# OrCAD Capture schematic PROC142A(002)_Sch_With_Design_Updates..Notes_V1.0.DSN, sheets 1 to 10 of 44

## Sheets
1 28. AUTOMATION SIGNALS BUFFER: size C; title: AUTOMATION SIGNALS BUFFER; rev: A1
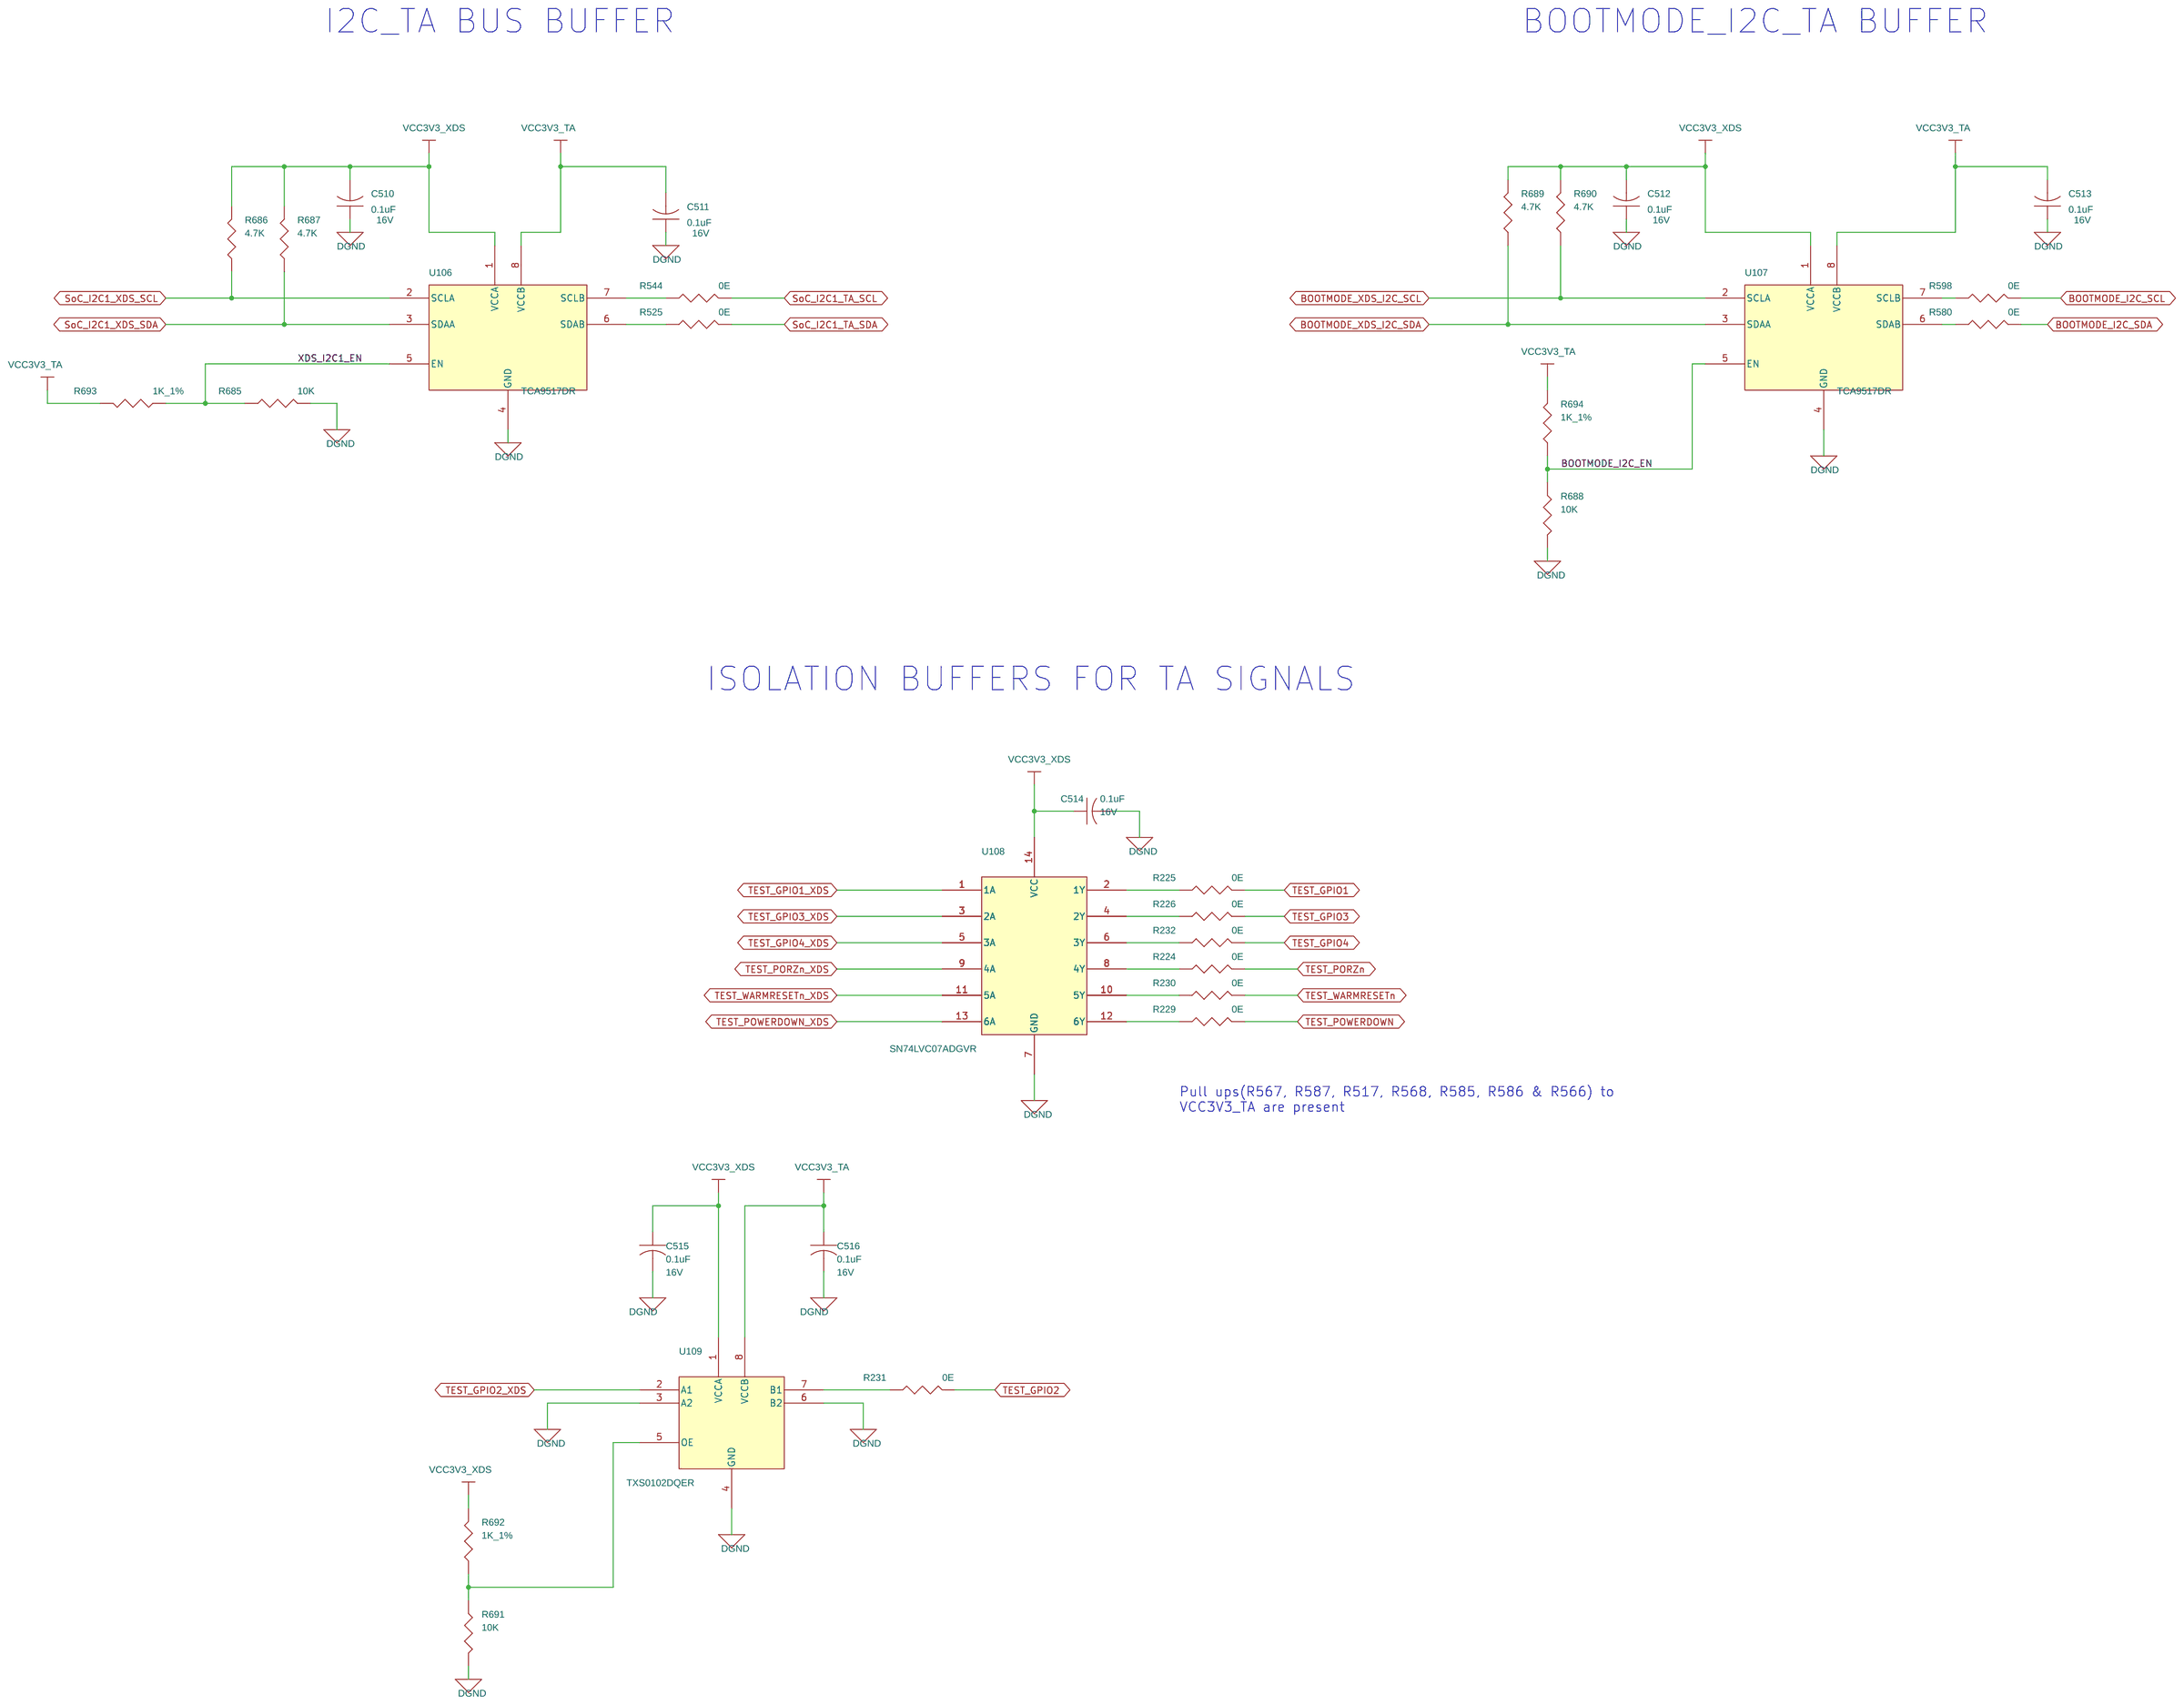
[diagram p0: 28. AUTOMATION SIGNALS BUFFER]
2 01. TABLE OF CONTENTS: title: TABLE OF CONTENTS
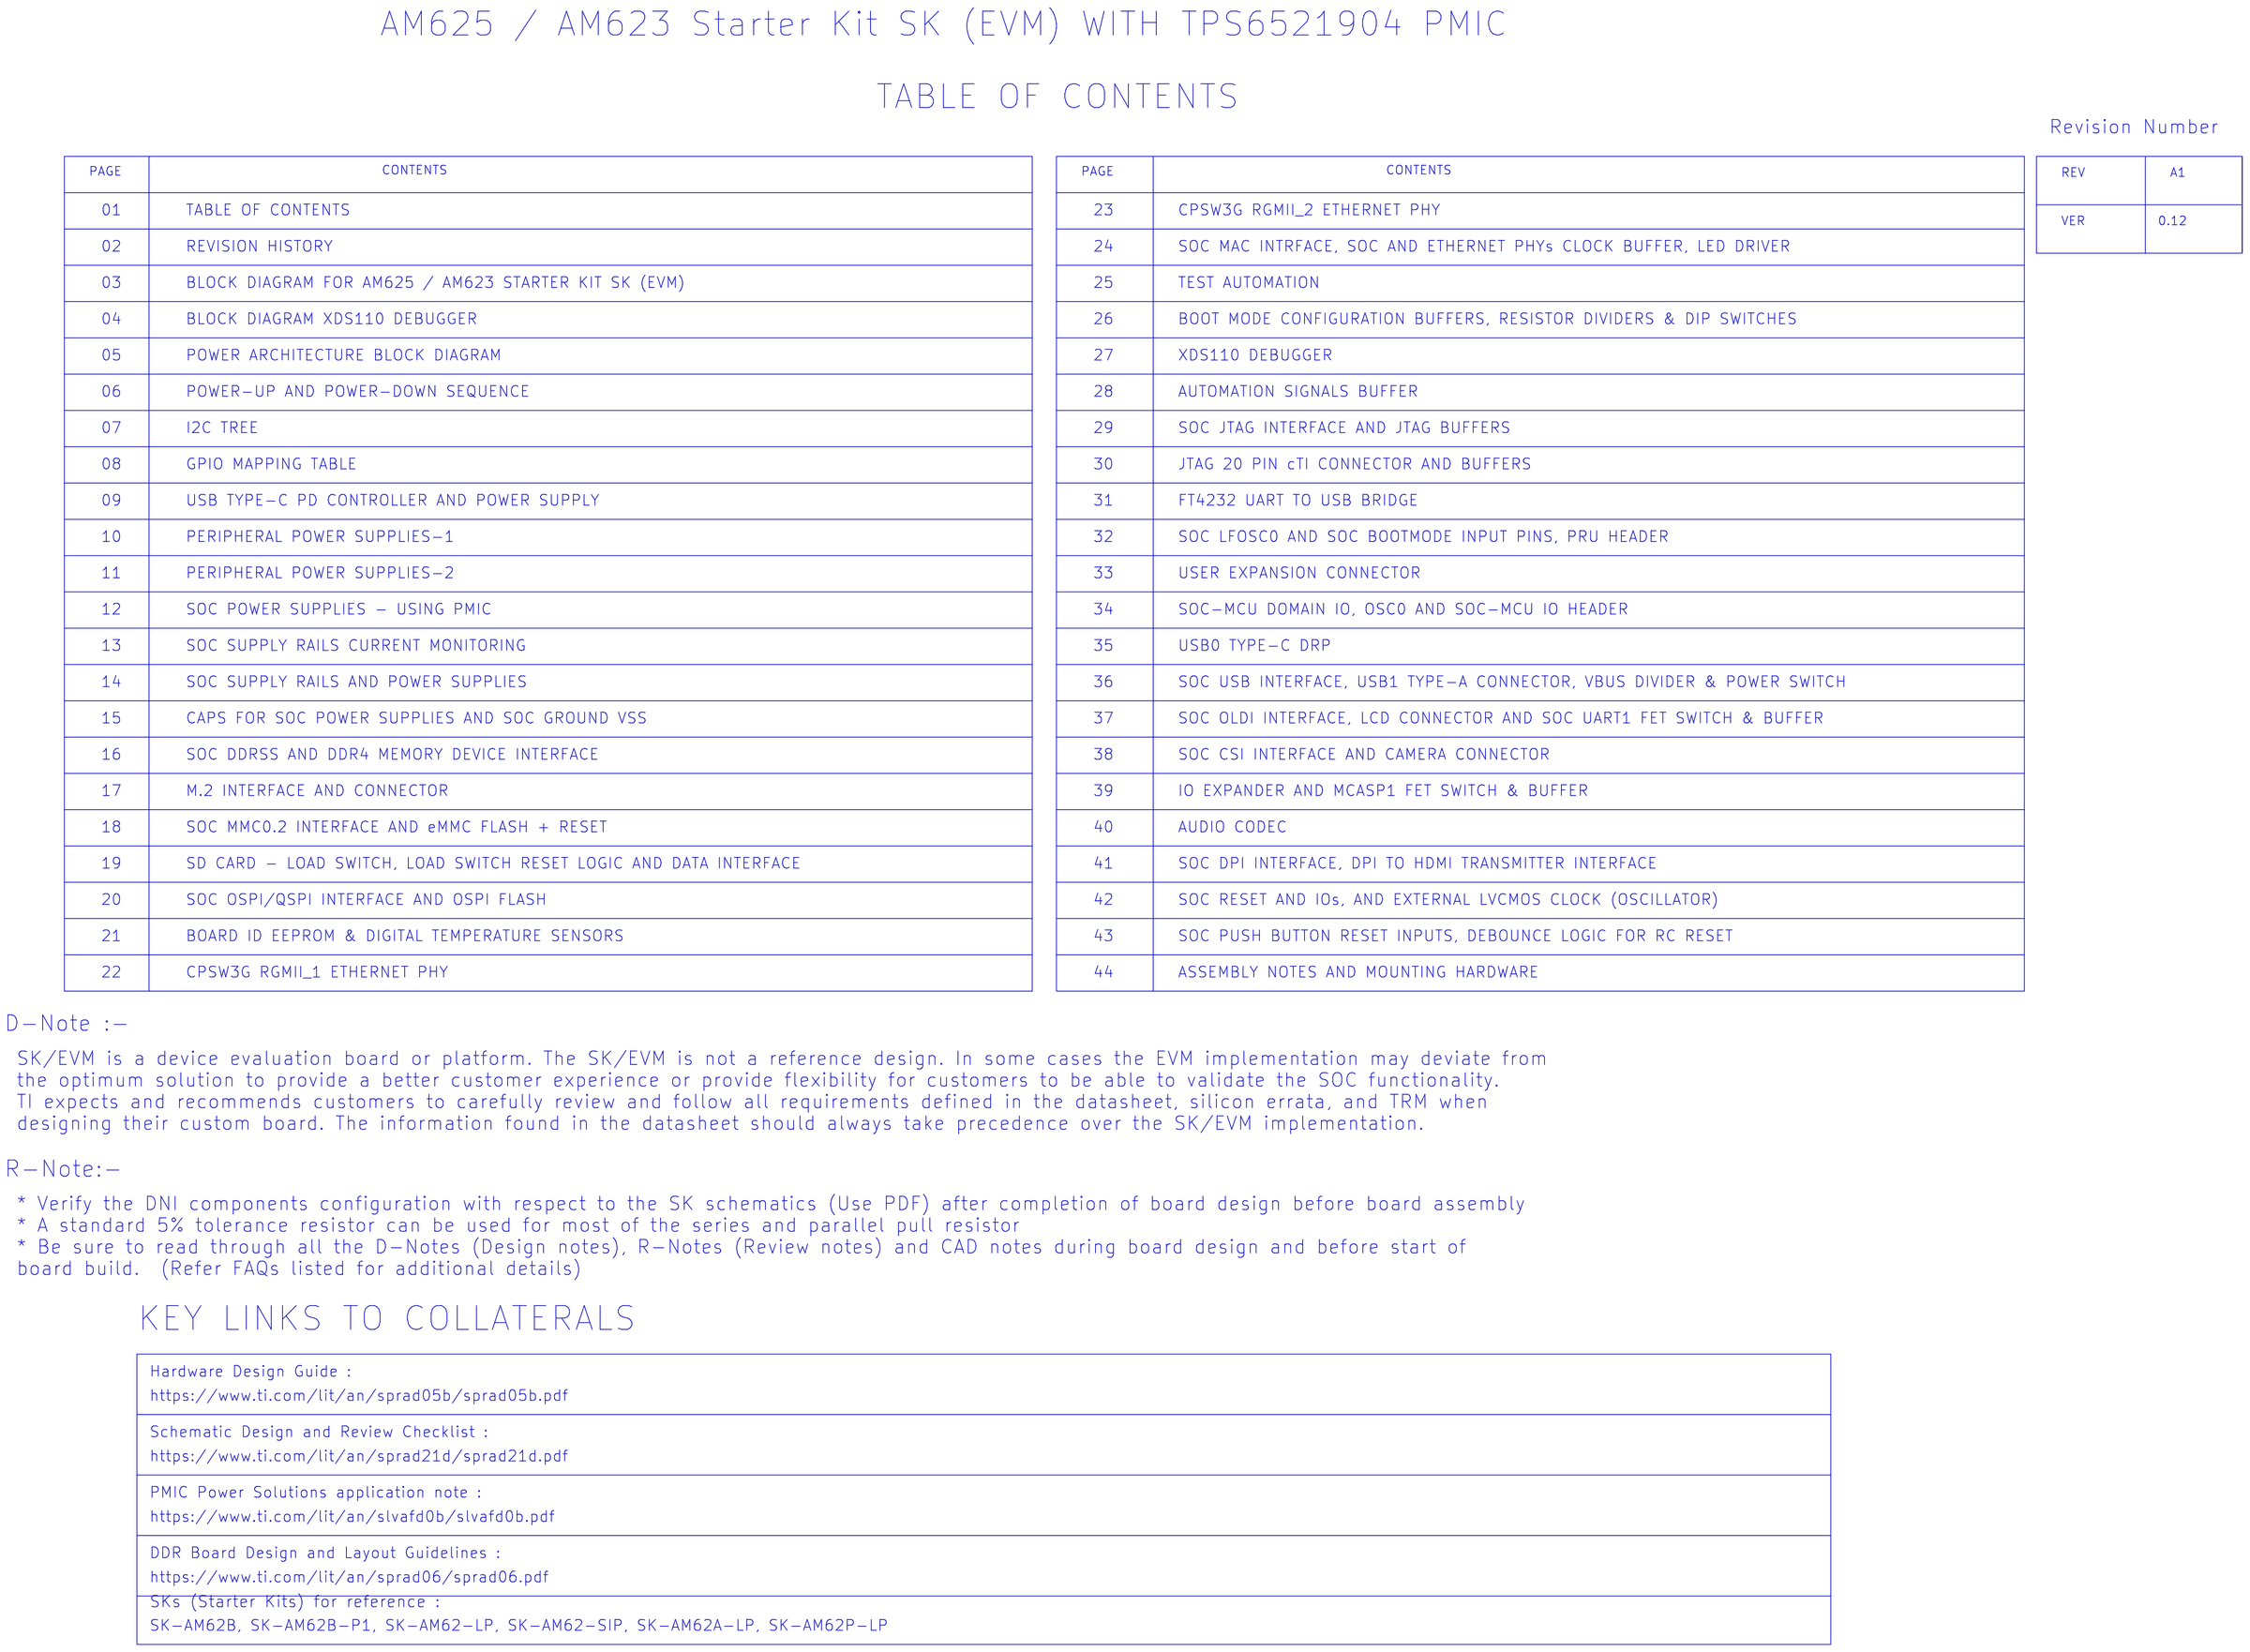
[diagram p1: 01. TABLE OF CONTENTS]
3 02. REVISION HISTORY: title: REVISION HISTORY
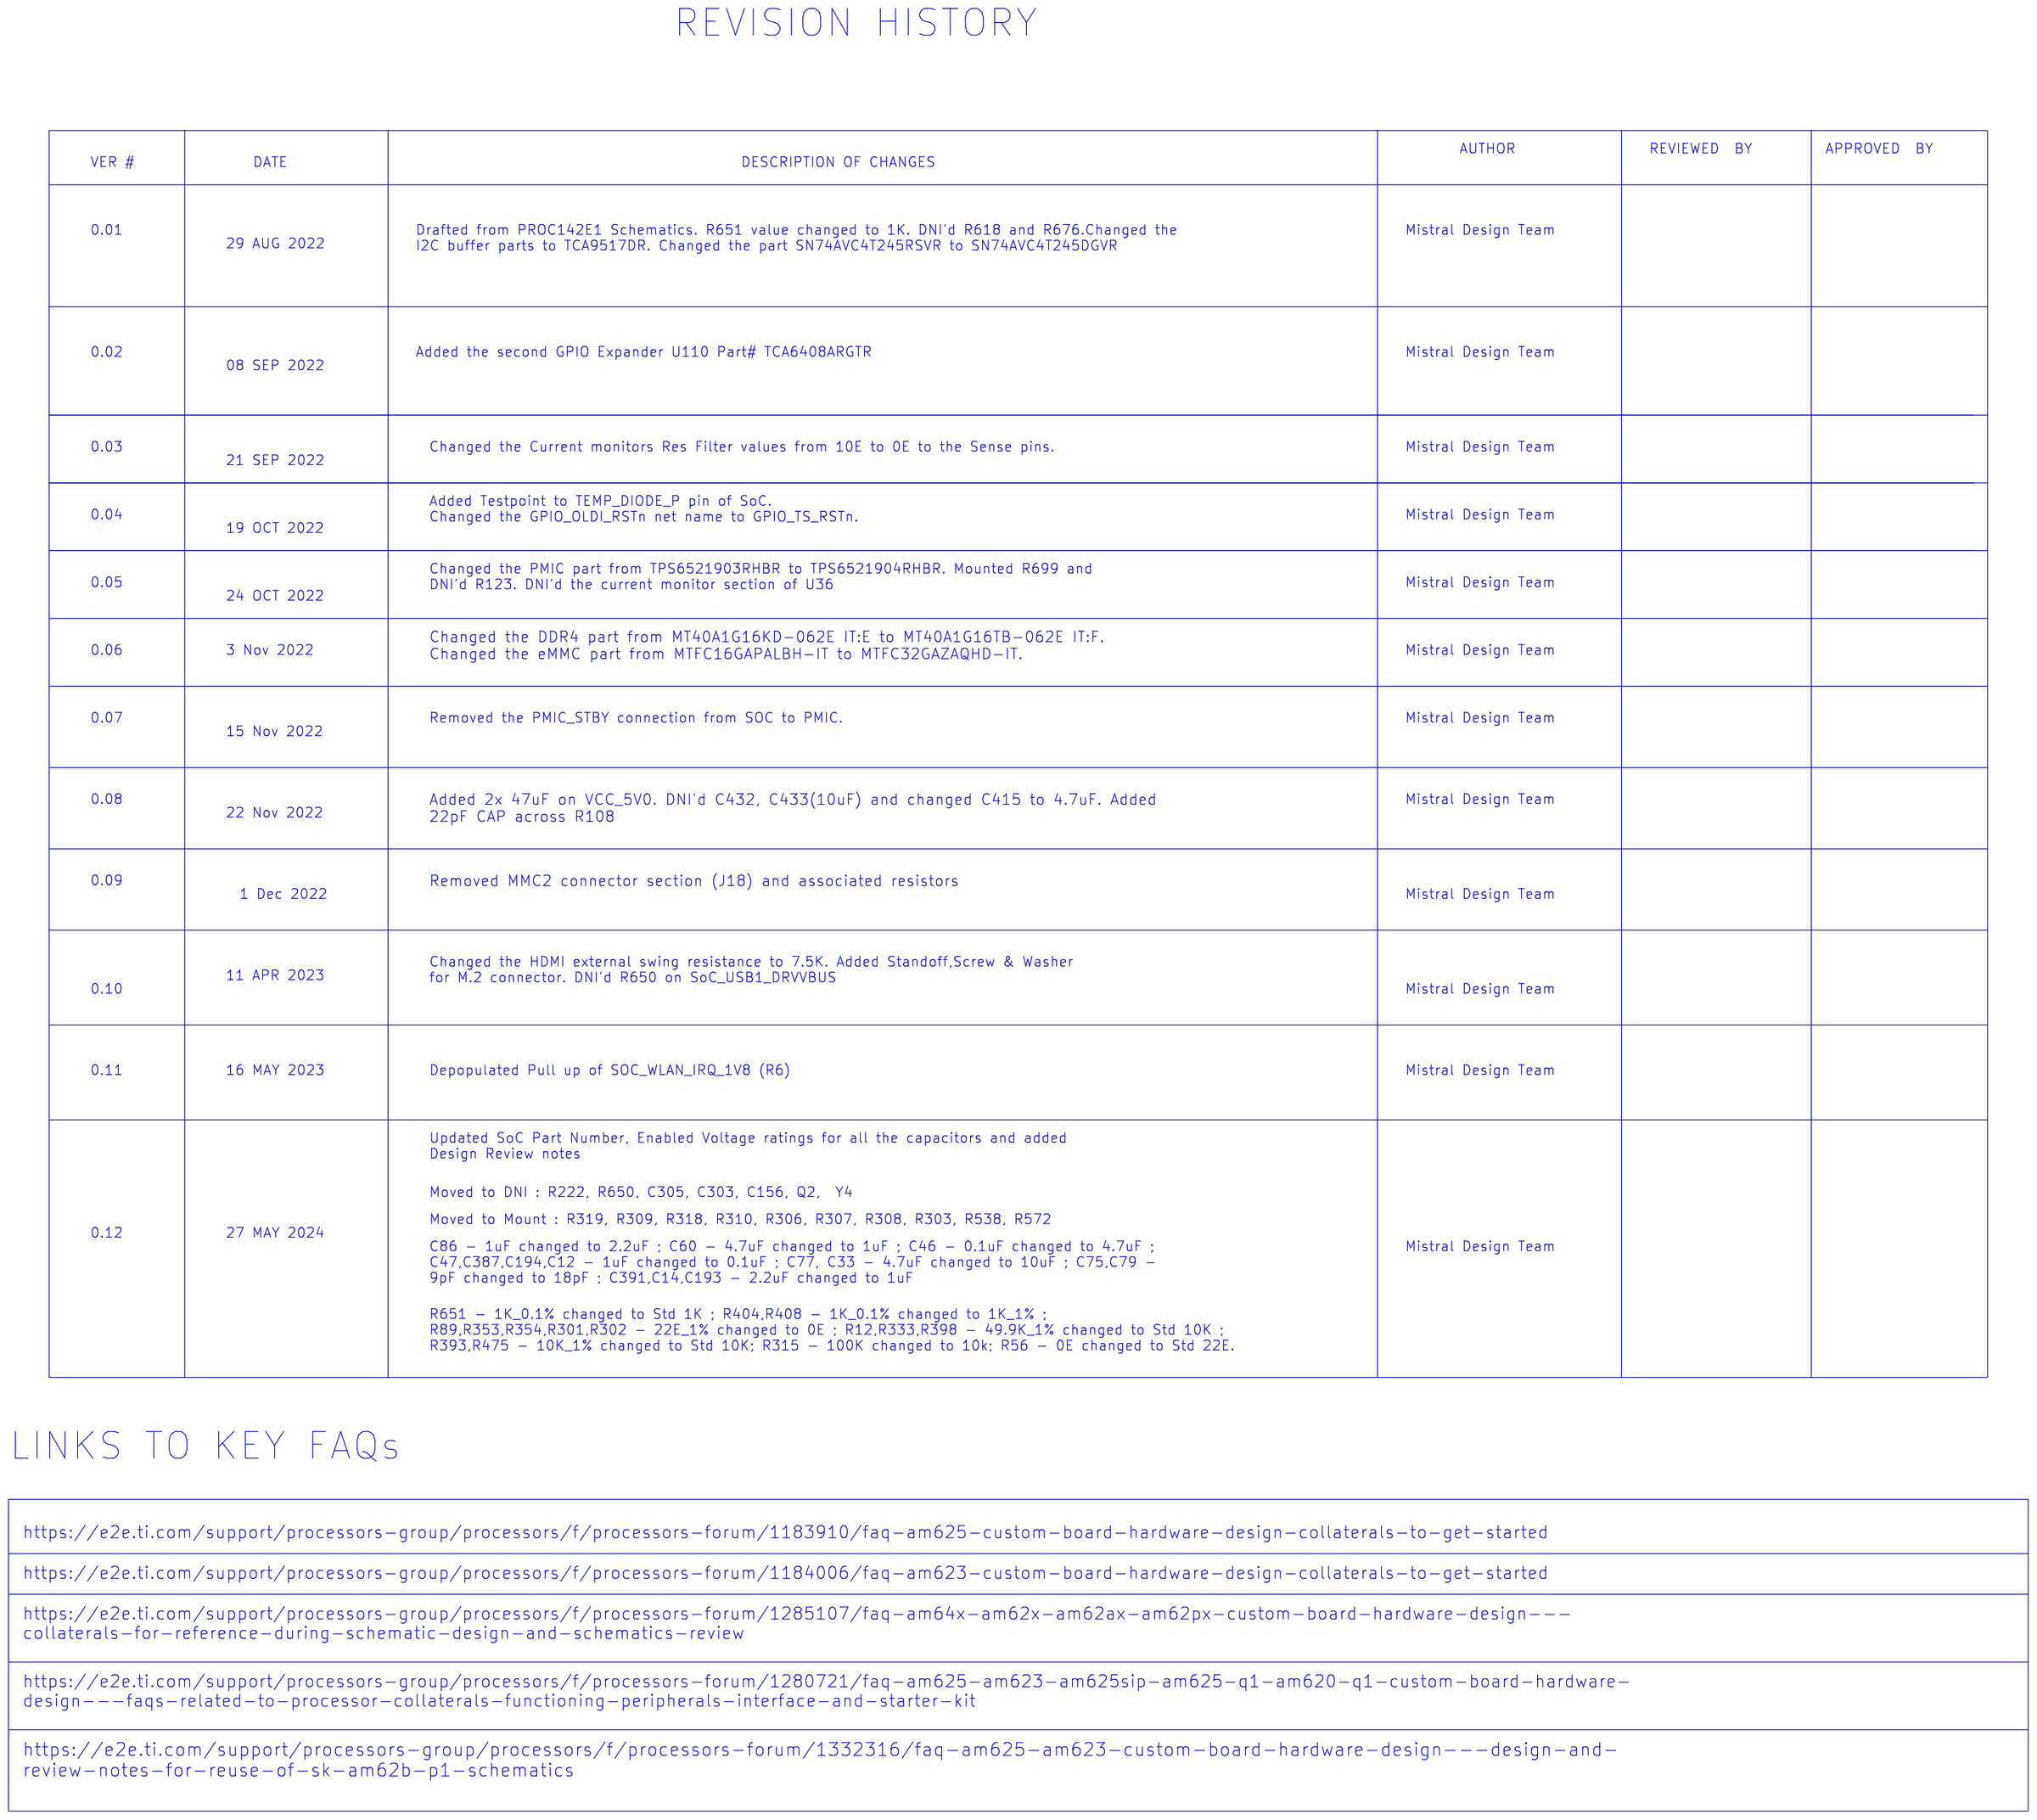
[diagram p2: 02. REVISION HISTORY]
4 03. BLOCK DIAGRAM AM62x_SKEVM: title: BLOCK DIAGRAM AM62x SKEVM
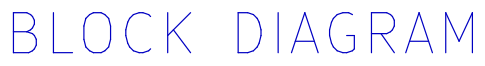
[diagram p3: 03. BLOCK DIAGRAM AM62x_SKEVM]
5 04. BLOCK DIAGRAM_XDS110: title: BLOCK DIAGRAM_XDS110
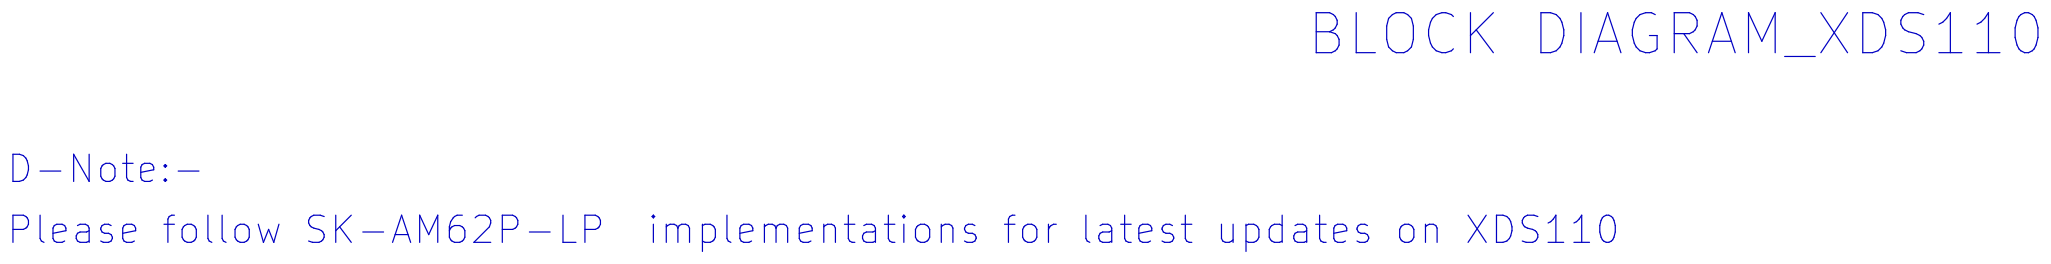
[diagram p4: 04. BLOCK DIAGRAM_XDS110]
6 05. POWER BLOCK DIAGRAM: title: POWER BLOCK DIAGRAM
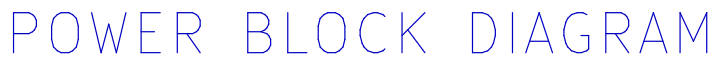
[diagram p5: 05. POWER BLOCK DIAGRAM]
7 06. POWER SEQUENCE: title: POWER SEQUENCE
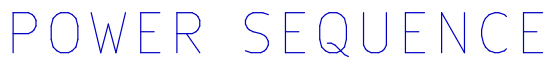
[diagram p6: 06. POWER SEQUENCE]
8 07. I2C TREE: title: I2C TREE
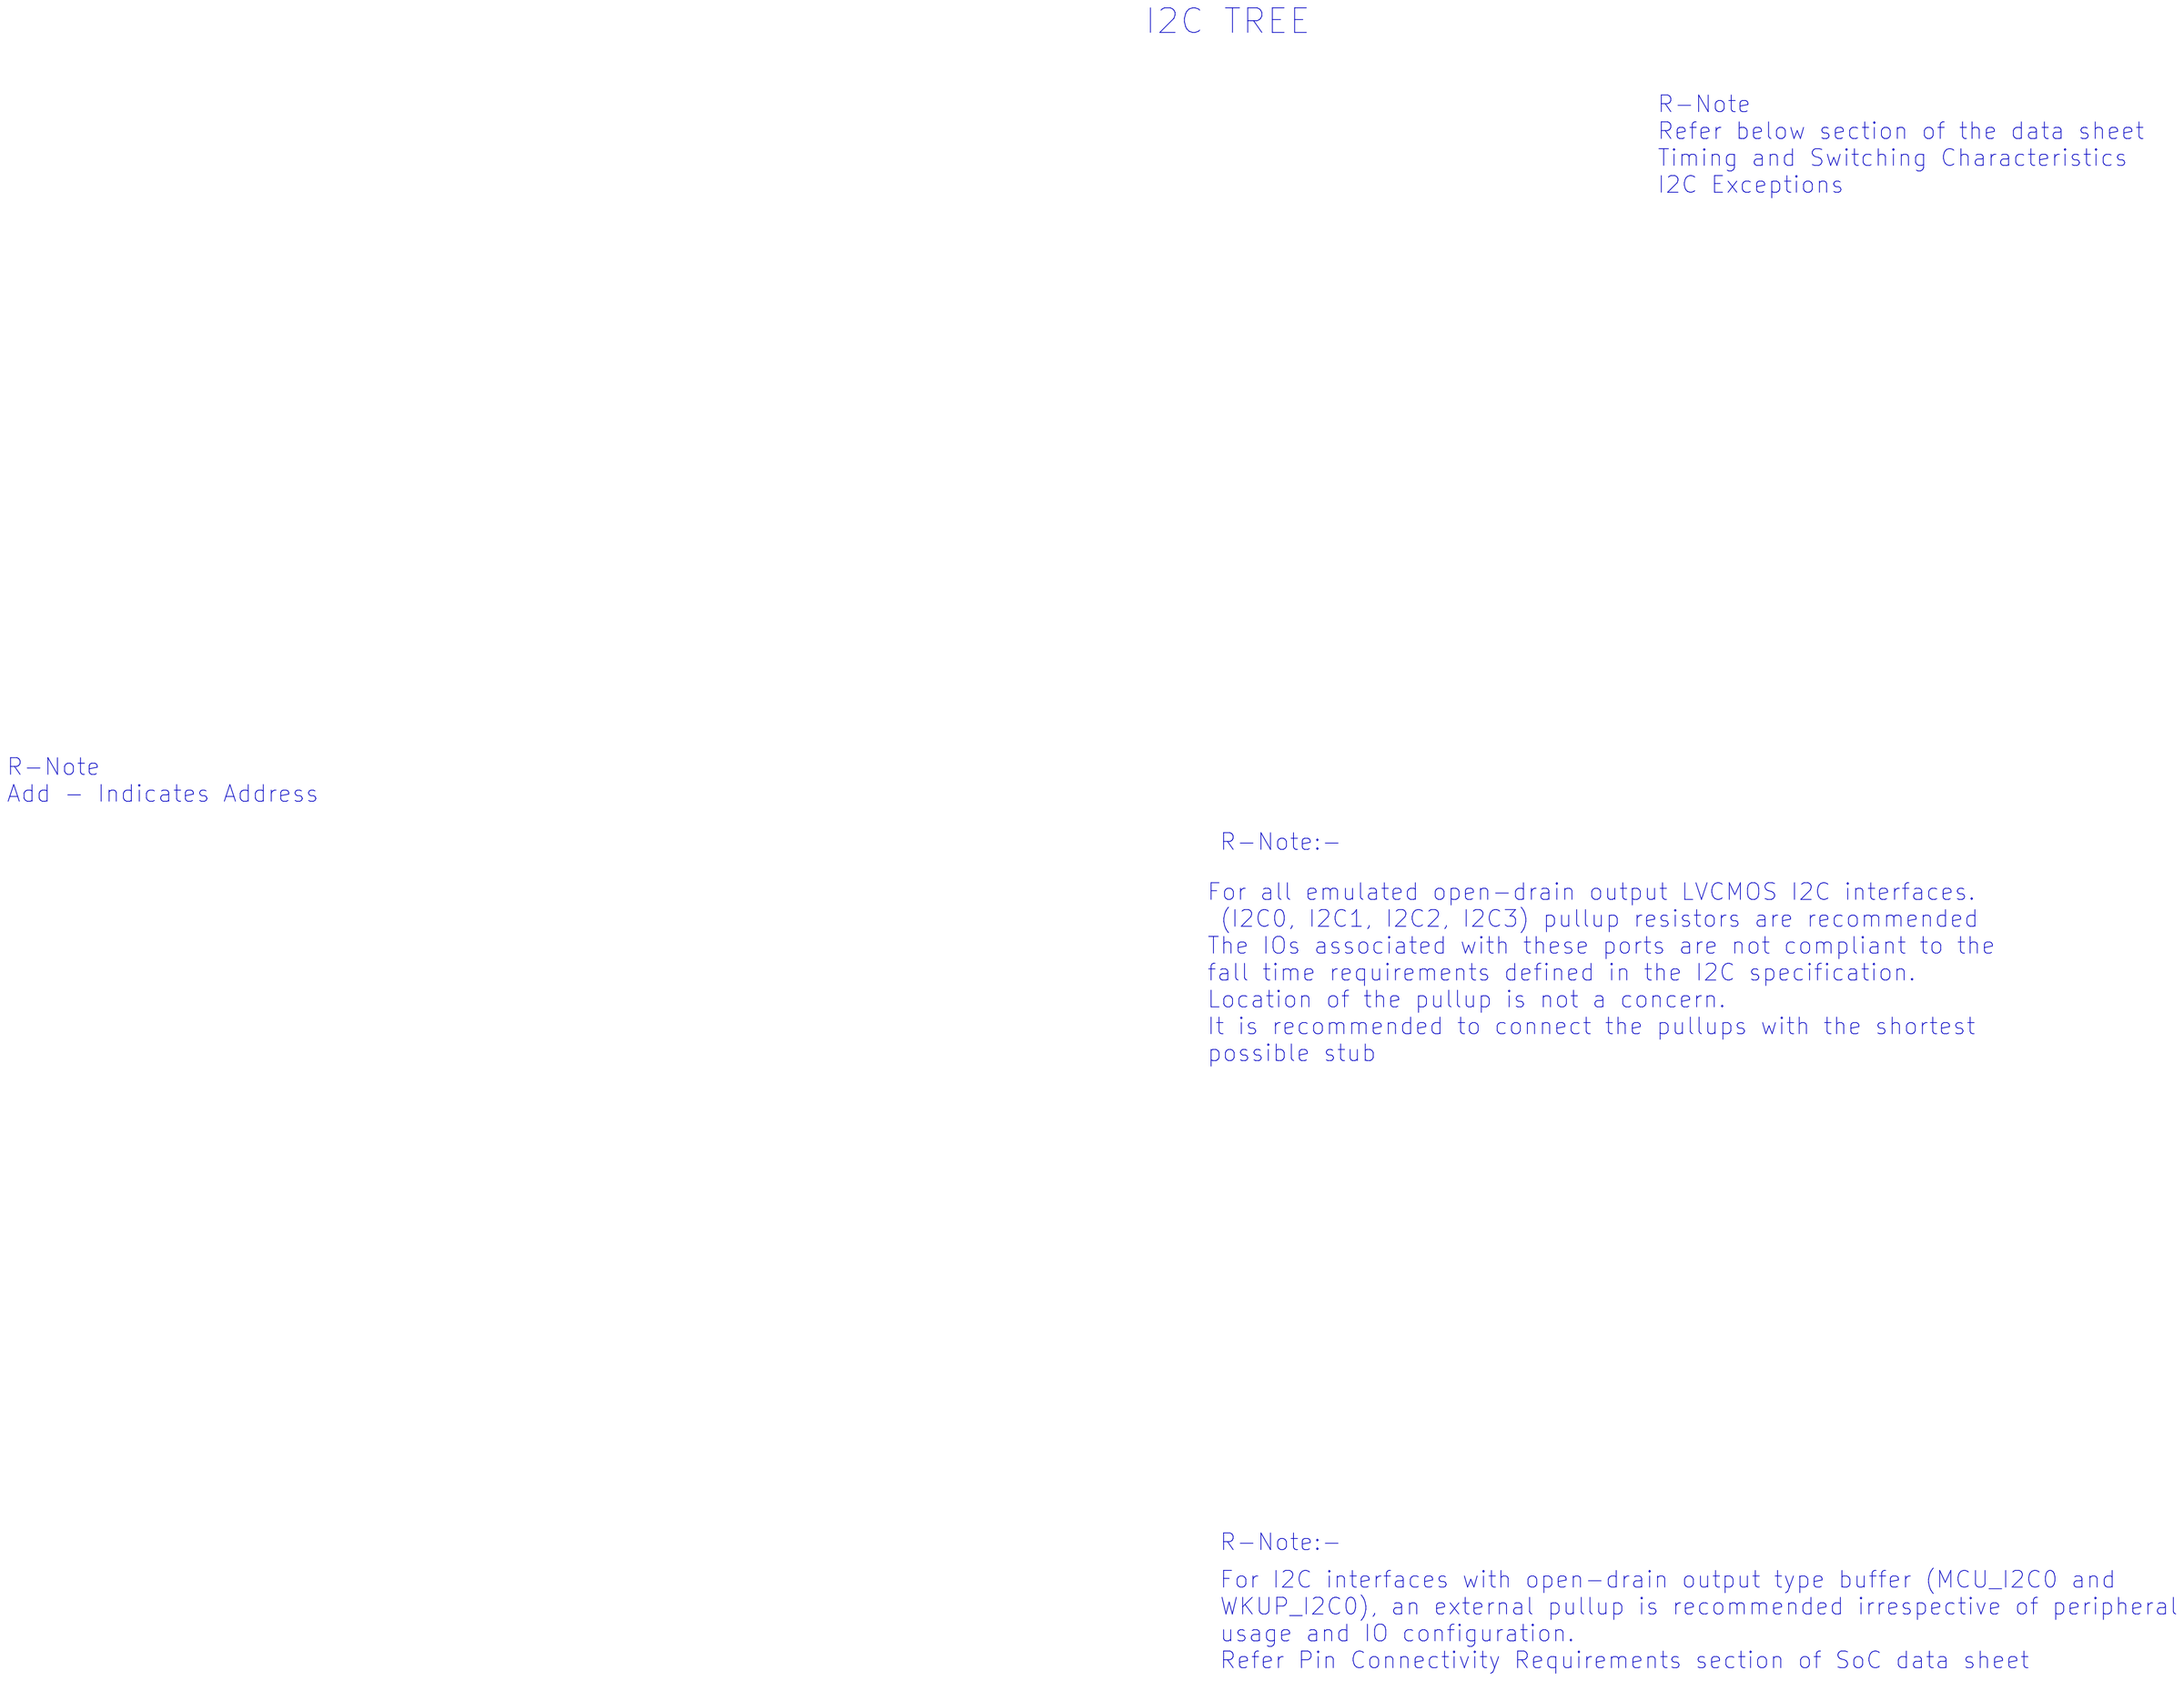
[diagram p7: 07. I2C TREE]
9 08. GPIO MAPPING TABLE: title: GPIO MAPPING TABLE
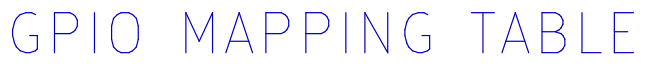
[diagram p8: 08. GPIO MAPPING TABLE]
10 09. USB TYPE-C POWER: size C; title: USB TYPE-C POWER
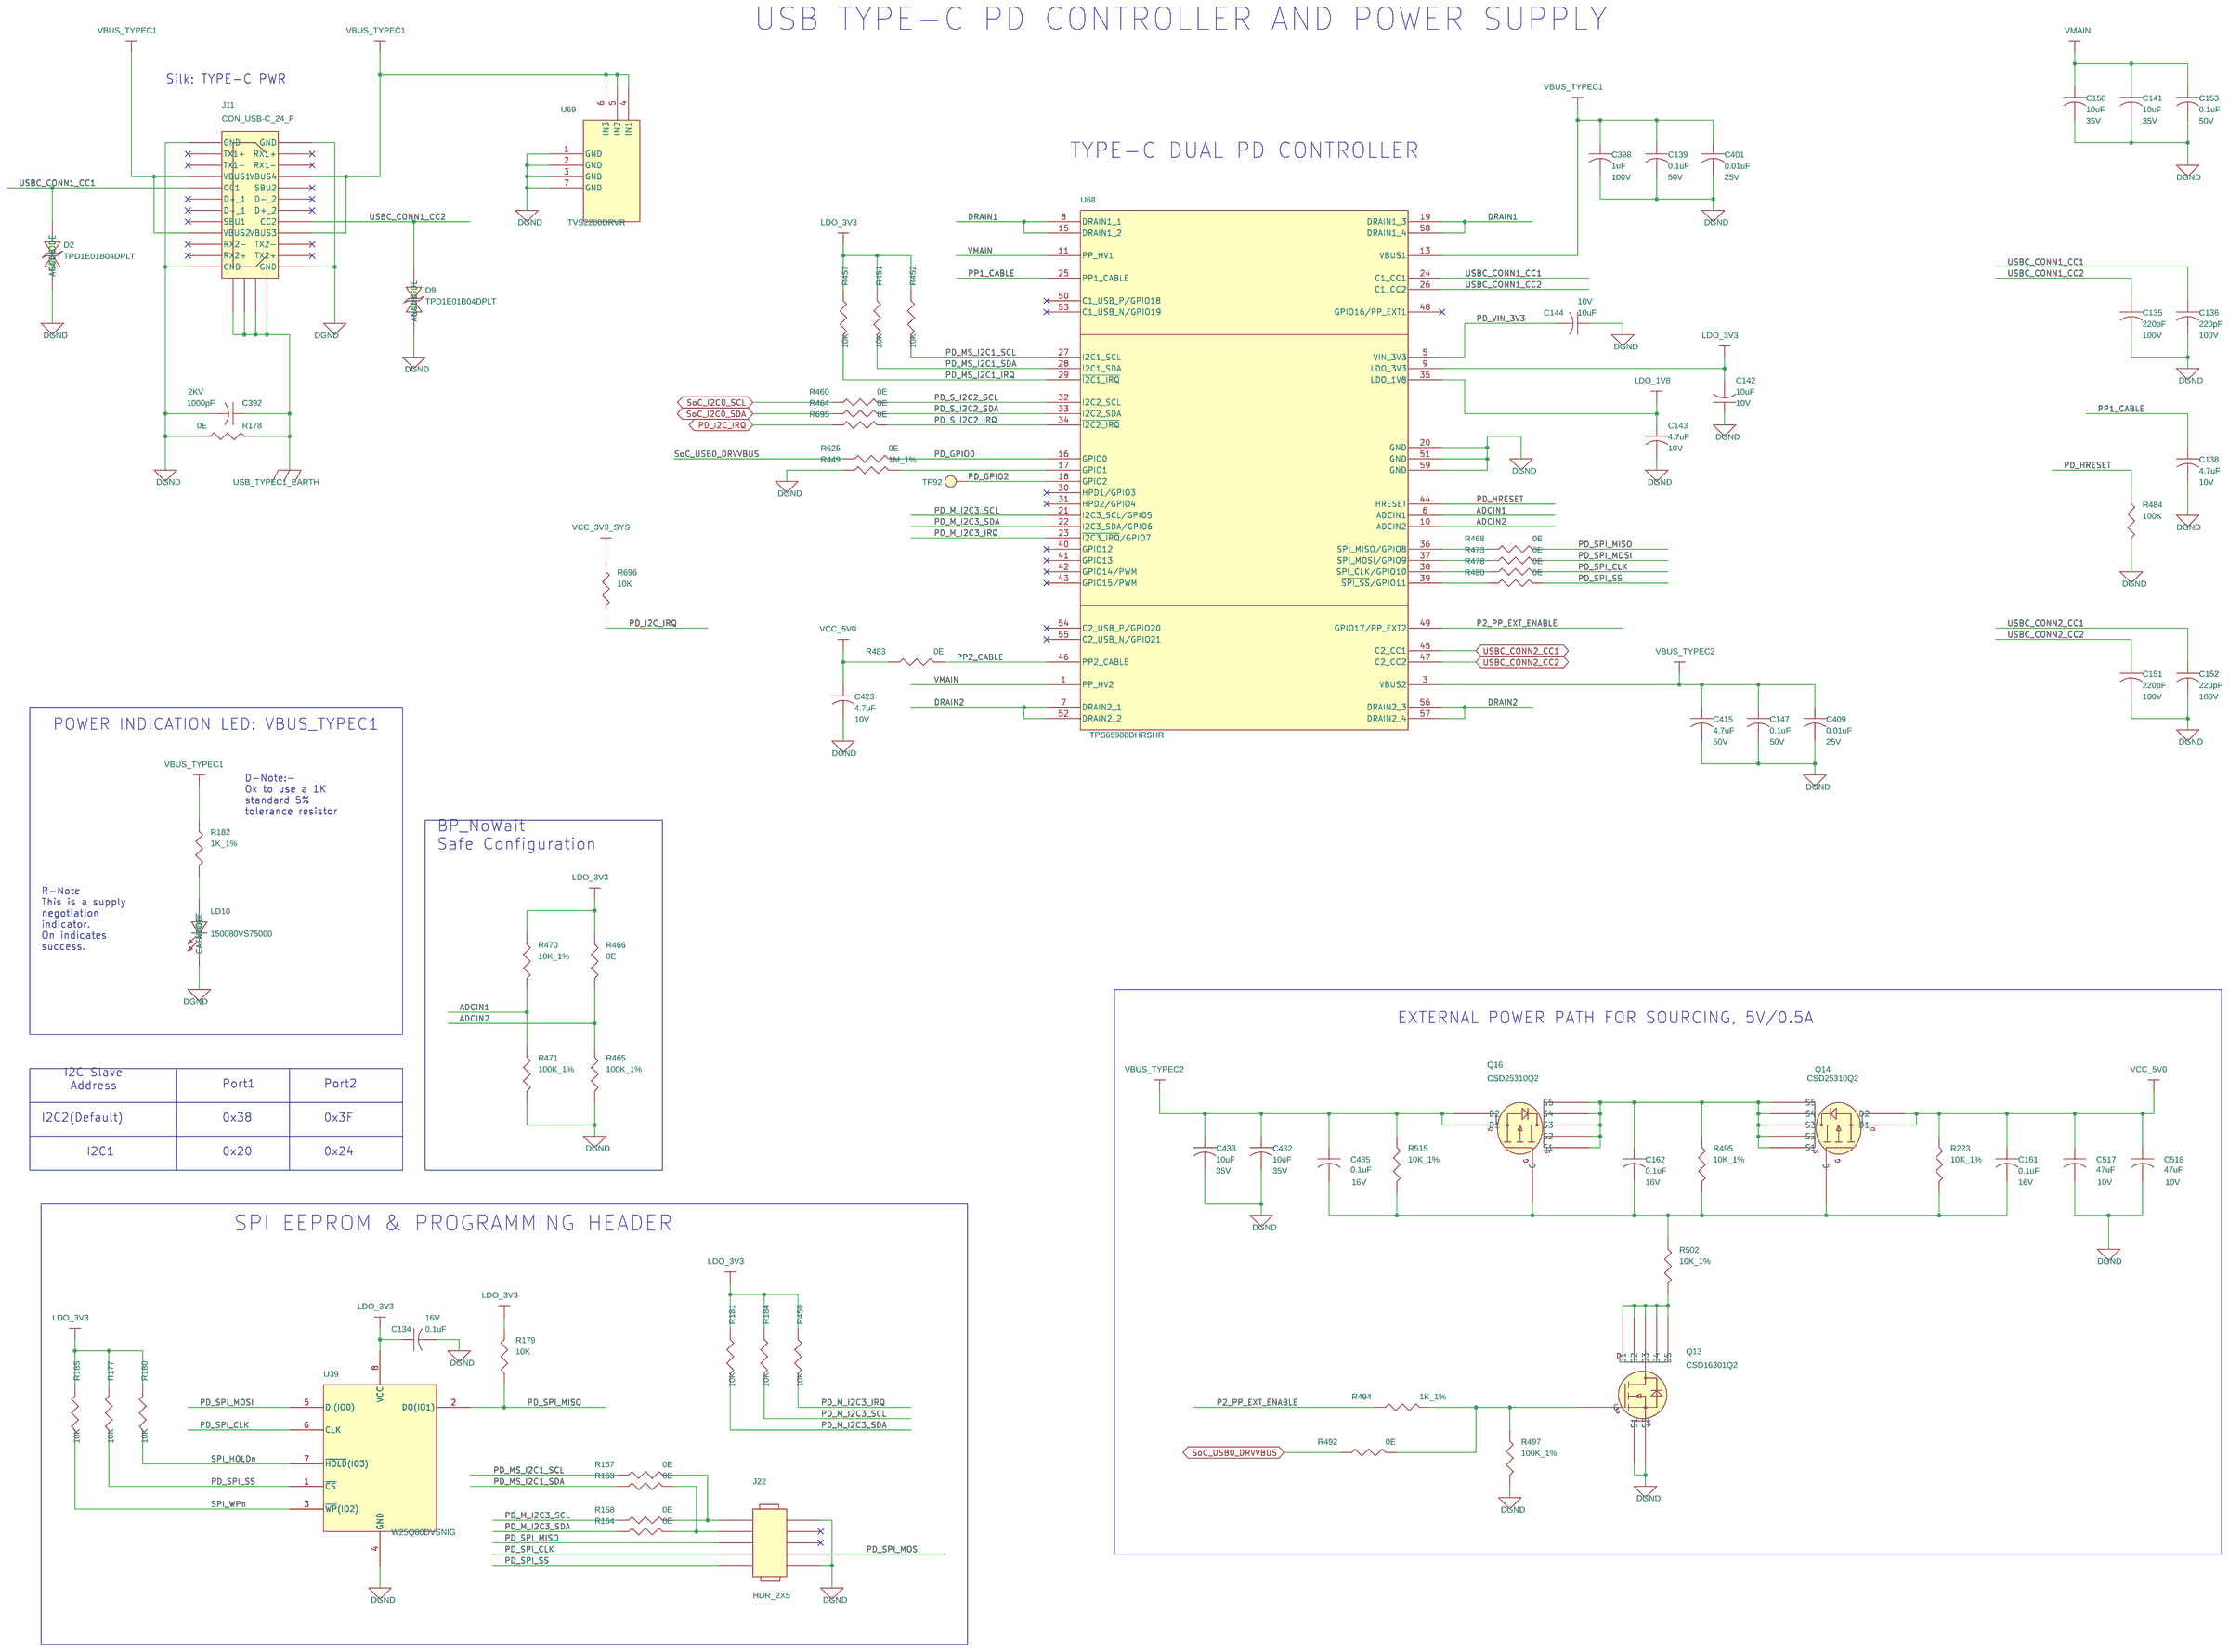
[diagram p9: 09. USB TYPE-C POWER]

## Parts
sheet 09. USB TYPE-C POWER
C134  0.1uF  [CAP0201_0-5]
C135  220pF  [CAP0402_0-75]
C136  220pF  [CAP0402_0-75]
C138  4.7uF  [CAP0402_0-75]
C139  0.1uF  [CAP0402_0-75]
C141  10uF  [CAP0603_1]
C142  10uF  [CAP0402_0-75]
C143  4.7uF  [CAP0402_0-75]
C144  10uF  [CAP0402_0-75]
C147  0.1uF  [CAP0402_0-75]
C150  10uF  [CAP0603_1]
C151  220pF  [CAP0402_0-75]
C152  220pF  [CAP0402_0-75]
C153  0.1uF  [CAP0402_0-75]
C161  0.1uF  [CAP0201_0-5]
C162  0.1uF  [CAP0201_0-5]
C392  1000pF  [CAP1206_1-75]
C398  1uF  [CAP0805_1-5]
C401  0.01uF  [CAP0201_0-5]
C409  0.01uF  [CAP0201_0-5]
C415  4.7uF  [CAP0805_1-5]
C423  4.7uF  [CAP0402_0-75]
C432  10uF  [CAP0603_1]
C433  10uF  [CAP0603_1]
C435  0.1uF  [CAP0201_0-5]
C517  47uF  [CAP1206_2]
C518  47uF  [CAP1206_2]
D2  TPD1E01B04DPLT  [DIO_DFN0201_0-4]
D9  TPD1E01B04DPLT  [DIO_DFN0201_0-4]
J11  CON_USB-C_24_F  [CON_USBC24_2012670_S_R_S_3-9]
J22  HDR_2X5  [HDR_2X5_PEC05DAAN_S_T_8-6]
LD10  150080VS75000  [LED_150080VS75000_80X50_SMD_0-8]
Q13  CSD16301Q2  [WSON6_CSD13202Q2_80X80_0-8]
Q14  CSD25310Q2  [SON6_CSD17313Q2_80X80]
Q16  CSD25310Q2  [SON6_CSD17313Q2_80X80]
R157  0E  [RES0201_0-5]
R158  0E  [RES0201_0-5]
R163  0E  [RES0201_0-5]
R164  0E  [RES0201_0-5]
R177  10K  [RES0201_0-5]
R178  0E  [RES0603_0-75]
R179  10K  [RES0201_0-5]
R180  10K  [RES0201_0-5]
R181  10K  [RES0201_0-5]
R182  1K_1%  [RES0402_0-5]
R184  10K  [RES0201_0-5]
R185  10K  [RES0201_0-5]
R223  10K_1%  [RES0201_0-5]
R449  1M_1%  [RES0402_0-5]
R450  10K  [RES0201_0-5]
R451  10K  [RES0201_0-5]
R452  10K  [RES0201_0-5]
R457  10K  [RES0201_0-5]
R460  0E  [RES0201_0-5]
R464  0E  [RES0201_0-5]
R465  100K_1%  [RES0402_0-5]
R466  0E  [RES0201_0-5]
R468  0E  [RES0201_0-5]
R470  10K_1%  [RES0201_0-5]
R471  100K_1%  [RES0402_0-5]
R473  0E  [RES0201_0-5]
R478  0E  [RES0201_0-5]
R480  0E  [RES0201_0-5]
R483  0E  [RES0402_0-5]
R484  100K  [RES0201_0-5]
R492  0E  [RES0201_0-5]
R494  1K_1%  [RES0402_0-5]
R495  10K_1%  [RES0201_0-5]
R497  100K_1%  [RES0402_0-5]
R502  10K_1%  [RES0201_0-5]
R515  10K_1%  [RES0201_0-5]
R625  0E  [RES0201_0-5]
R695  0E  [RES0201_0-5]
R696  10K  [RES0201_0-5]
TP92  TP20_SMD  [TP20_SMD]
U39  W25Q80DVSNIG  [SOIC8_1-8]
U68  TPS65988DHRSHR  [VQFN56_TPS65987D_280X280_1]
U69  TVS2200DRVR  [SON6_25-59_85X85_0-8]
sheet 28. AUTOMATION SIGNALS BUFFER
C510  0.1uF  [CAP0201_0-5]
C511  0.1uF  [CAP0201_0-5]
C512  0.1uF  [CAP0201_0-5]
C513  0.1uF  [CAP0201_0-5]
C514  0.1uF  [CAP0201_0-5]
C515  0.1uF  [CAP0201_0-5]
C516  0.1uF  [CAP0201_0-5]
R224  0E  [RES0201_0-5]
R225  0E  [RES0201_0-5]
R226  0E  [RES0201_0-5]
R229  0E  [RES0201_0-5]
R230  0E  [RES0201_0-5]
R231  0E  [RES0201_0-5]
R232  0E  [RES0201_0-5]
R525  0E  [RES0201_0-5]
R544  0E  [RES0201_0-5]
R580  0E  [RES0201_0-5]
R598  0E  [RES0201_0-5]
R685  10K  [RES0201_0-5]
R686  4.7K  [RES0201_0-5]
R687  4.7K  [RES0201_0-5]
R688  10K  [RES0201_0-5]
R689  4.7K  [RES0201_0-5]
R690  4.7K  [RES0201_0-5]
R691  10K  [RES0201_0-5]
R692  1K_1%  [RES0402_0-5]
R693  1K_1%  [RES0402_0-5]
R694  1K_1%  [RES0402_0-5]
U106  TCA9517DR  [SOIC8_1-8]
U107  TCA9517DR  [SOIC8_1-8]
U108  SN74LVC07ADGVR  [TVSOP14_15-74_180X150_1-2]
U109  TXS0102DQER  [X2SON8_TXS0102_40X60_0-4]

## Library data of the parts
C134 C161 C162 C435 = CAP: CAP CERAMIC 0.1uF 16V 10% X5R 0201; Chkd/date: MANIRAJA/230118; Crtd /date: MANIRAJA/230118; Custom_Duty: 15%; Customs_HS_Code: 85322990; Distributor_name: DIGIKEY; Distributor_part_number: 490-14305-1-ND; Footprint Path: Y:\MIS_DATABASE\Library\ALTIUM_TOOL\PCB_FOOTPRINTS\Altium_Footprint_Lib.PcbLib; Height: 0.33MM; Library Path: Y:\MIS_DATABASE\Library\ALTIUM_TOOL\SCHEMATICS_PARTS\MS_DISCRETE_Library.schlib; Mfr_name: MURATA; Mfr_part_number: GRM033R61C104KE14D; Mistral Part No: 120009030072-R; Package: 0201; Part_type: CAPACITORS\CERAMIC; Project: TI_MAXIE_CPB; RoHS: RoHS; Temperature: -55°C+85°C; Tolerance: 10%; Voltage: 16V; Wattage: NA; Weight: 0.33mg; Datasheet: Y:\MIS_DATABASE\DATASHEETS\CAPACITORS\GRM033R61C104KE14.PDF
C135 C136 C151 C152 = CAP: CAP CERAMIC 220pF 100V 5% C0G(NP0) 0402; Chkd/date: MANIRAJA/061021; Crtd /date: ALVY/051021; Custom_Duty: 15%; Customs_HS_Code: 85322990; Distributor_name: DIGIKEY; Distributor_part_number: 490-GRM1555C2A221JE01DTR-ND; Footprint Path: Y:\MIS_DATABASE\Library\ALTIUM_TOOL\PCB_FOOTPRINTS\Altium_Footprint_Lib.PcbLib; Height: 0.55MM; Library Path: Y:\MIS_DATABASE\Library\ALTIUM_TOOL\SCHEMATICS_PARTS\MS_DISCRETE_Library.schlib; Mfr_name: MURATA; Mfr_part_number: GRM1555C2A221JE01D; Mistral Part No: 120021100001-R; Package: 0402; Part_type: CAPACITORS\CERAMIC; Project: TI_AM62x SKEVM_BRD; RoHS: RoHS; Temperature: -55°C+125°C; Tolerance: 5%; Voltage: 100V; Wattage: NA; Weight: 1.6mg; Datasheet: Y:\MIS_DATABASE\DATASHEETS\CAPACITORS\GRM1555C2A221JE01.PDF
C138 C143 C423 = CAP: CAP CERAMIC 4.7uF 10V 20% X5R 0402; Chkd/date: MANIRAJA/110718; Crtd /date: ALVY/110718; Custom_Duty: 15%; Customs_HS_Code: 85322990; Distributor_name: DIGIKEY; Distributor_part_number: 490-14306-1-ND; Footprint Path: Y:\MIS_DATABASE\Library\ALTIUM_TOOL\PCB_FOOTPRINTS\Altium_Footprint_Lib.PcbLib; Height: 0.65MM; Library Path: Y:\MIS_DATABASE\Library\ALTIUM_TOOL\SCHEMATICS_PARTS\MS_DISCRETE_Library.schlib; Mfr_name: MURATA; Mfr_part_number: GRM155R61A475MEAAD; Mistral Part No: 120012060002-R; Package: 0402; Part_type: CAPACITORS\CERAMIC; Project: TI_J7SVB_PCIE_ADD-ON-CARD; RoHS: RoHS; Temperature: -55°C+85°C; Tolerance: 20%; Voltage: 10V; Wattage: NA; Weight: 14mg; Datasheet: Y:\MIS_DATABASE\DATASHEETS\CAPACITORS\GRM155R61A475MEAAD.PDF
C139 C147 C153 = CAP: CAP CERAMIC 0.1uF 50V 10% X7R 0402; Chkd/date: MANIRAJA/261020; Crtd /date: ALVY/211020; Custom_Duty: 15%; Customs_HS_Code: 85322990; Distributor_name: DIGIKEY; Distributor_part_number: 490-10700-1-ND; Footprint Path: Y:\MIS_DATABASE\Library\ALTIUM_TOOL\PCB_FOOTPRINTS\Altium_Footprint_Lib.PcbLib; Height: 0.55MM; Library Path: Y:\MIS_DATABASE\Library\ALTIUM_TOOL\SCHEMATICS_PARTS\MS_DISCRETE_Library.schlib; Mfr_name: MURATA; Mfr_part_number: GRM155R71H104KE14D; Mistral Part No: 120011100014-R; Package: 0402; Part_type: CAPACITORS\CERAMIC; Project: J7_CP; RoHS: RoHS; Temperature: -55°C+125°C; Tolerance: 10%; Voltage: 50V; Wattage: NA; Weight: 3.1mg; Datasheet: Y:\MIS_DATABASE\DATASHEETS\CAPACITORS\GRM155R71H104KE14.PDF
C141 C150 C432 C433 = CAP: CAP CERAMIC 10uF 35V 20% X5R 0603; Chkd/date: MANIRAJA/170519; Crtd /date: ALVY/160519; Custom_Duty: 15%; Customs_HS_Code: 85322990; Distributor_name: DIGIKEY; Distributor_part_number: 490-13248-1-ND; Footprint Path: Y:\MIS_DATABASE\Library\ALTIUM_TOOL\PCB_FOOTPRINTS\Altium_Footprint_Lib.PcbLib; Height: 1.00MM; Library Path: Y:\MIS_DATABASE\Library\ALTIUM_TOOL\SCHEMATICS_PARTS\MS_DISCRETE_Library.schlib; Mfr_name: MURATA; Mfr_part_number: GRM188R6YA106MA73D; Mistral Part No: 120019050016-R; Package: 0603; Part_type: CAPACITORS\CERAMIC; Project: BRUKER_SD820_COMMONDO; RoHS: RoHS; Temperature: -55°C+85°C; Tolerance: 20%; Voltage: 35V; Wattage: NA; Weight: 9mg; Datasheet: Y:\MIS_DATABASE\DATASHEETS\CAPACITORS\GRM188R6YA106MA73.PDF
C142 C144 = CAP: CAP CERAMIC 10uF 10V 20% X5R 0402; Chkd/date: MANIRAJA/300520; Crtd /date: ALVY/260520; Custom_Duty: 15%; Customs_HS_Code: 85322990; Distributor_name: DIGIKEY; Distributor_part_number: 490-GRM155R61A106ME11DTR-ND; Footprint Path: Y:\MIS_DATABASE\Library\ALTIUM_TOOL\PCB_FOOTPRINTS\Altium_Footprint_Lib.PcbLib; Height: 0.55MM; Library Path: Y:\MIS_DATABASE\Library\ALTIUM_TOOL\SCHEMATICS_PARTS\MS_DISCRETE_Library.schlib; Mfr_name: MURATA; Mfr_part_number: GRM155R61A106ME11D; Mistral Part No: 120013110019-R; Package: 0402; Part_type: CAPACITORS\CERAMIC; Project: QCS610_NANOSOM; RoHS: RoHS; Temperature: -55°C+85°C; Tolerance: 20%; Voltage: 10V; Wattage: NA; Weight: 3.1mg; Datasheet: Y:\MIS_DATABASE\DATASHEETS\CAPACITORS\MURATA-GXX-SER_NOV17.PDF
C392 = CAP: CAP CERAMIC 1000pF 2KV 10% X7R 1206; Chkd/date: SHREESHAIL/291106; Crtd /date: MAZHAR/281106; Custom_Duty: 15%; Customs_HS_Code: 85322990; Distributor_name: DIGIKEY; Distributor_part_number: 478-2956-1-ND; Footprint Path: Y:\MIS_DATABASE\Library\ALTIUM_TOOL\PCB_FOOTPRINTS\Altium_Footprint_Lib.PcbLib; Height: 1.52MM; Library Path: Y:\MIS_DATABASE\Library\ALTIUM_TOOL\SCHEMATICS_PARTS\MS_DISCRETE_Library.schlib; Mfr_name: AVX CORPORATION; Mfr_part_number: 1206GC102KAT1A; Mistral Part No: 120015080006-R; Package: 1206; Part_type: CAPACITORS\CERAMIC; Project: ADR1B; RoHS: RoHS; Temperature: -55°C+125°C; Tolerance: 10%; Voltage: 2KV; Wattage: NA; Weight: 16.2mg; Datasheet: Y:\MIS_DATABASE\DATASHEETS\CAPACITORS\AVX_HV-MLC.PDF
C398 = CAP: CAP CERAMIC 1uF 100V 10% X7S 0805; Chkd/date: MANIRAJA/160921; Crtd /date: ALVY/150921; Custom_Duty: 15%; Customs_HS_Code: 85322990; Distributor_name: DIGIKEY; Distributor_part_number: 490-14464-1-ND; Footprint Path: Y:\MIS_DATABASE\Library\ALTIUM_TOOL\PCB_FOOTPRINTS\Altium_Footprint_Lib.PcbLib; Height: 1.45MM; Library Path: Y:\MIS_DATABASE\Library\ALTIUM_TOOL\SCHEMATICS_PARTS\MS_DISCRETE_Library.schlib; Mfr_name: MURATA; Mfr_part_number: GRM21BC72A105KE01L; Mistral Part No: 120013030002-R; Package: 0805; Part_type: CAPACITORS\CERAMIC; Project: TI_AM62x SKEVM_BRD; RoHS: RoHS; Temperature: -55°C+125°C; Tolerance: 10%; Voltage: 100V; Wattage: NA; Weight: 6.4mg; Datasheet: Y:\MIS_DATABASE\DATASHEETS\CAPACITORS\GRM21BC72A105KE01.PDF
C401 C409 = CAP: CAP CERAMIC 0.01uF 25V 10% X5R 0201; Chkd/date: MANIRAJA/230118; Crtd /date: MANIRAJA/230118; Custom_Duty: 15%; Customs_HS_Code: 85322990; Distributor_name: DIGIKEY; Distributor_part_number: GRM033R61E103KA12J-ND; Footprint Path: Y:\MIS_DATABASE\Library\ALTIUM_TOOL\PCB_FOOTPRINTS\Altium_Footprint_Lib.PcbLib; Height: 0.33MM; Library Path: Y:\MIS_DATABASE\Library\ALTIUM_TOOL\SCHEMATICS_PARTS\MS_DISCRETE_Library.schlib; Mfr_name: MURATA; Mfr_part_number: GRM033R61E103KA12J; Mistral Part No: 120018010007-R; Package: 0201; Part_type: CAPACITORS\CERAMIC; Project: TI_MAXIE_CPB; RoHS: RoHS; Temperature: -55°C+85°C; Tolerance: 10%; Voltage: 25V; Wattage: NA; Weight: 0.33mg; Datasheet: Y:\MIS_DATABASE\DATASHEETS\CAPACITORS\GRM033R61E103KA12.PDF
C415 = CAP: CAP CERAMIC 4.7uF 50V 10% X5R 0805; Chkd/date: VASANTHA/281216; Crtd /date: BAVISH/290711; Custom_Duty: 15%; Customs_HS_Code: 85322990; Distributor_name: DIGIKEY; Distributor_part_number: 445-5980-1-ND; Footprint Path: Y:\MIS_DATABASE\Library\ALTIUM_TOOL\PCB_FOOTPRINTS\Altium_Footprint_Lib.PcbLib; Height: 1.45MM; Library Path: Y:\MIS_DATABASE\Library\ALTIUM_TOOL\SCHEMATICS_PARTS\MS_DISCRETE_Library.schlib; Mfr_name: TDK CORPORATION; Mfr_part_number: C2012X5R1H475K; Mistral Part No: 120011070010-R; Package: 0805; Part_type: CAPACITORS\CERAMIC; Project: OMAPL1_PEC20; RoHS: RoHS; Temperature: -55°C+85°C; Tolerance: 10%; Voltage: 50V; Wattage: NA; Weight: 5.5mg; Datasheet: Y:\MIS_DATABASE\DATASHEETS\CAPACITORS\TDK_C-SERIES.PDF
C517 C518 = CAP: CAP CERAMIC 47uF 10V 20% X5R 1206; Chkd/date: USMAN/121213; Crtd /date: USMAN/121213; Custom_Duty: 15%; Customs_HS_Code: 85322990; Distributor_name: DIGIKEY; Distributor_part_number: 490-5528-1-ND; Footprint Path: Y:\MIS_DATABASE\Library\ALTIUM_TOOL\PCB_FOOTPRINTS\Altium_Footprint_Lib.PcbLib; Height: 1.80MM; Library Path: Y:\MIS_DATABASE\Library\ALTIUM_TOOL\SCHEMATICS_PARTS\MS_DISCRETE_Library.schlib; Mfr_name: MURATA; Mfr_part_number: GRM31CR61A476ME15L; Mistral Part No: 120013120015-R; Package: 1206; Part_type: CAPACITORS\CERAMIC; Project: DMP; RoHS: RoHS; Temperature: -55°C+85°C; Tolerance: 20%; Voltage: 10V; Wattage: NA; Weight: 40mg; Datasheet: Y:\MIS_DATABASE\DATASHEETS\CAPACITORS\MURATA-GXX-SER_NOV17.PDF
D2 D9 = DIODE_TVS_DUAL: DIODE 1CH ESD PROTECTION FOR USB TYPE-C AND THUNDERBOLT3 X2SON2; Chkd/date: MANIRAJA/230920; Crtd /date: ALVY/230920; Custom_Duty: 15%; Customs_HS_Code: 85412900; Distributor_name: DIGIKEY; Distributor_part_number: 296-44484-1-ND; Footprint Path: Y:\MIS_DATABASE\Library\ALTIUM_TOOL\PCB_FOOTPRINTS\Altium_Footprint_Lib.PcbLib; Height: 0.32MM; Library Path: Y:\MIS_DATABASE\Library\ALTIUM_TOOL\SCHEMATICS_PARTS\MS_DISCRETE_Library.schlib; Mfr_name: TEXAS INSTRUMENTS; Mistral Part No: 130020090037-R; Package: X2SON2; Part_type: DIODE\TVS; Project: AM64X_SKEVM; RoHS: RoHS; Temperature: -40°C+125°C; Tolerance: NA; Voltage: NA; Wattage: NA; Weight: 0.2mg; Datasheet: Y:\MIS_DATABASE\DATASHEETS\DISCRETES\DIODES\TPD1E01B04.PDF
J11 = CON_USB-C_24_1240183621: CON USB-C TYPE 24POS FEMALE RT SMD; Chkd/date: MANIRAJA/050618; Crtd /date: ALVY/040618; Custom_Duty: 24%; Customs_HS_Code: 85369090; Distributor_name: DIGIKEY; Distributor_part_number: WM17992CT-ND; Footprint Path: Y:\MIS_DATABASE\Library\ALTIUM_TOOL\PCB_FOOTPRINTS\Altium_Footprint_Lib.PcbLib; Height: 3.86MM; Library Path: Y:\MIS_DATABASE\Library\ALTIUM_TOOL\SCHEMATICS_PARTS\MS_CONNECTOR_Library.schlib; Mfr_name: MOLEX; Mfr_part_number: 2012670005; Mistral Part No: 150018060002-R; Package: SMD; Part_type: CONNECTOR\USB; Project: TI_J7SVB_USB_ADD-ON-CARD; RoHS: RoHS; Temperature: -40°C+105°C; Tolerance: NA; Voltage: NA; Wattage: NA; Weight: 0.686g; Datasheet: Y:\MIS_DATABASE\DATASHEETS\CONNECTORS\2012670X.PDF
J22 = HEADER_5X2: CON HDR 2X5 2.54MM PITCH ST TH; Chkd/date: MANIRAJA/060821; Crtd /date: ALVY/060821; Custom_Duty: 24%; Customs_HS_Code: 85369090; Distributor_name: DIGIKEY; Distributor_part_number: S2012E-05-ND; Footprint Path: Y:\MIS_DATABASE\Library\ALTIUM_TOOL\PCB_FOOTPRINTS\Altium_Footprint_Lib.PcbLib; Height: 8.58MM; Library Path: Y:\MIS_DATABASE\Library\ALTIUM_TOOL\SCHEMATICS_PARTS\MS_CONNECTOR_Library.schlib; Mfr_name: SULLINS CONNECTOR; Mfr_part_number: PEC05DAAN; Mistral Part No: 150021080010-R; Package: THRU-HOLE; Part_type: CONNECTOR\HEADERS; Project: TI_AM335x SK_BRD; RoHS: RoHS; Temperature: -65°C+125°C; Tolerance: NA; Voltage: NA; Wattage: NA; Weight: NA; Datasheet: Y:\MIS_DATABASE\DATASHEETS\CONNECTORS\XXCXXDXXN.PDF
LD10 = DIODE_LED: DIODE LED BRIGHT GREEN SMD; Chkd/date: MANIRAJA/180820; Crtd /date: ALVY/180820; Custom_Duty: 24%; Customs_HS_Code: 85439000; Distributor_name: DIGIKEY; Distributor_part_number: 732-4986-1-ND; Footprint Path: Y:\MIS_DATABASE\Library\ALTIUM_TOOL\PCB_FOOTPRINTS\Altium_Footprint_Lib.PcbLib; Height: 0.80MM; Library Path: Y:\MIS_DATABASE\Library\ALTIUM_TOOL\SCHEMATICS_PARTS\MS_OPTO_Library.schlib; Mfr_name: WURTH ELECTRONICS; Mistral Part No: 130020080012-R; Package: SMD; Part_type: OPTO\LED; Project: AM64x_EVM_BRD; RoHS: RoHS; Temperature: -40°C+85°C; Tolerance: NA; Voltage: NA; Wattage: NA; Weight: 10mg; Datasheet: Y:\MIS_DATABASE\DATASHEETS\DISCRETES\LEDS\150080VS75000.PDF
Q13 = MOSFET_CSD17313Q2: IC MOSFET N-CHANNEL NEXFET 25V WSON6; Chkd/date: ALVY/071220; Crtd /date: MANIRAJA/071220; Custom_Duty: 15%; Customs_HS_Code: 85423100; Distributor_name: DIGIKEY; Distributor_part_number: 296-25260-1-ND; Footprint Path: Y:\MIS_DATABASE\Library\ALTIUM_TOOL\PCB_FOOTPRINTS\Altium_Footprint_Lib.PcbLib; Height: 0.80MM; Library Path: Y:\MIS_DATABASE\Library\ALTIUM_TOOL\SCHEMATICS_PARTS\MS_MOSFET_Library.schlib; Mfr_name: TEXAS INSTRUMENTS; Mistral Part No: 142020120008-R; Package: WSON6; Part_type: ICS\POWER\MOSFET; Project: TI_AM243x LP EVM; RoHS: RoHS; Temperature: -55°C+150°C; Tolerance: NA; Voltage: NA; Wattage: NA; Weight: 8.7mg; Datasheet: Y:\MIS_DATABASE\DATASHEETS\ICS\POWER\CSD16301Q2.PDF
Q14 Q16 = MOSFET_CSD25310Q2: IC MOSFET P-CHANNEL WSON6; Chkd/date: VASANTHA/191215; Crtd /date: VASANTHA/191215; Custom_Duty: 15%; Customs_HS_Code: 85423100; Distributor_name: DIGIKEY; Distributor_part_number: 296-38915-1-ND; Height: 0.85MM; Mfr_name: TEXAS INSTRUMENTS; Mistral Part No: 142015120011-R; Package: WSON6; Part_type: ICS\POWER\MOSFET; Project: DUET BOARD; RoHS: RoHS; Temperature: -55°C+150°C; Tolerance: NA; Voltage: NA; Wattage: NA; Weight: NA; Datasheet: Y:\MIS_DATABASE\DATASHEETS\DISCRETES\TRANSISTORS_FETS\CSD25310Q2.PDF
R157 R158 R163 R164 R224-R226 R229-R232 R460 R464 R468 R473 R478 R480 R492 R525 R544 R580 R598 R625 R695 = RESISTOR: RES 0E 1/20W 5% 0201; Chkd/date: NAVEED/301214; Crtd /date: MUDDU/120710; Custom_Duty: 15%; Customs_HS_Code: 85332119; Distributor_name: DIGIKEY; Distributor_part_number: 311-0.0NCT-ND; Footprint Path: Y:\MIS_DATABASE\Library\ALTIUM_TOOL\PCB_FOOTPRINTS\Altium_Footprint_Lib.PcbLib; Height: 0.26MM; Library Path: Y:\MIS_DATABASE\Library\ALTIUM_TOOL\SCHEMATICS_PARTS\MS_DISCRETE_Library.schlib; Mfr_name: YAGEO AMERICA; Mfr_part_number: RC0201JR-070RL; Mistral Part No: 110010070067-R; Package: 0201; Part_type: RESISTORS\FIXED; Project: PB_BUGBASE; RoHS: RoHS; Temperature: -55°C+125°C; Tolerance: 5%; Voltage: NA; Wattage: 1/20W; Weight: 0.17mg; Datasheet: Y:\MIS_DATABASE\DATASHEETS\RESISTORS\RCXXXXL-SER_MAR18.PDF
R177 R179-R181 R184 R185 R450-R452 R457 R685 R688 R691 R696 = RESISTOR: RES 10K 1/20W 5% 0201; Chkd/date: MANIRAJA/050517; Crtd /date: MANIRAJA/050517; Custom_Duty: 15%; Customs_HS_Code: 85332119; Distributor_name: DIGIKEY; Distributor_part_number: 311-10KNCT-ND; Footprint Path: Y:\MIS_DATABASE\Library\ALTIUM_TOOL\PCB_FOOTPRINTS\Altium_Footprint_Lib.PcbLib; Height: 0.26MM; Library Path: Y:\MIS_DATABASE\Library\ALTIUM_TOOL\SCHEMATICS_PARTS\MS_DISCRETE_Library.schlib; Mfr_name: YAGEO AMERICA; Mfr_part_number: RC0201JR-0710KL; Mistral Part No: 110010070051-R; Package: 0201; Part_type: RESISTORS\FIXED; Project: GOLDEN-I LITE; RoHS: RoHS; Temperature: -55°C+125°C; Tolerance: 5%; Voltage: NA; Wattage: 1/20W; Weight: 0.17mg; Datasheet: Y:\MIS_DATABASE\DATASHEETS\RESISTORS\RCXXXXL-SER_MAR18.PDF
R178 = RESISTOR: RES 0E 1/10W 5% 0603; Chkd/date: MANIRAJA/051217; Crtd /date: BAVISH/180211; Custom_Duty: 15%; Customs_HS_Code: 85332119; Distributor_name: DIGIKEY; Distributor_part_number: 311-0.0GRCT-ND; Footprint Path: Y:\MIS_DATABASE\Library\ALTIUM_TOOL\PCB_FOOTPRINTS\Altium_Footprint_Lib.PcbLib; Height: 0.55MM; Library Path: Y:\MIS_DATABASE\Library\ALTIUM_TOOL\SCHEMATICS_PARTS\MS_DISCRETE_Library.schlib; Manufacturer: YAGEO AMERICA; Mfr_name: PANASONIC-ECG; Mfr_part_number: RC0603JR-070RL; Mistral Part No: 110011020013-R; Package: 0603; Part_type: RESISTORS\FIXED; Project: KENNEL; RoHS: RoHS; Temperature: -55°C+155°C; Tolerance: 5%; Voltage: NA; Wattage: 1/10W; Weight: 2mg; Datasheet: Y:\MIS_DATABASE\DATASHEETS\RESISTORS\RCXXXXL-SER_MAR18.PDF
R182 R494 R692-R694 = RESISTOR: RES 1K 1/10W 1% 0402; Chkd/date: VASANTHA/281216; Crtd /date: MAZHAR/150506; Custom_Duty: 15%; Customs_HS_Code: 85332119; Distributor_name: DIGIKEY; Distributor_part_number: P1.00KLCT-ND; Footprint Path: Y:\MIS_DATABASE\Library\ALTIUM_TOOL\PCB_FOOTPRINTS\Altium_Footprint_Lib.PcbLib; Height: 0.40MM; Library Path: Y:\MIS_DATABASE\Library\ALTIUM_TOOL\SCHEMATICS_PARTS\MS_DISCRETE_Library.schlib; Mfr_name: PANASONIC-ECG; Mfr_part_number: ERJ-2RKF1001X; Mistral Part No: 110009030411-R; Package: 0402; Part_type: RESISTORS\FIXED; Project: VOCERA; RoHS: RoHS; Temperature: -55°C+155°C; Tolerance: 1%; Voltage: NA; Wattage: 1/10W; Weight: 0.8mg; Datasheet: Y:\MIS_DATABASE\DATASHEETS\RESISTORS\PAN-ERJSER_NOV17.PDF
R223 R515 = RESISTOR: RES 10K 1/20W 1% 0201; Chkd/date: MANIRAJA/260618; Crtd /date: ALVY/260618; Custom_Duty: 15%; Customs_HS_Code: 85332119; Distributor_name: DIGIKEY; Distributor_part_number: 541-10.0KABCT-ND; Footprint Path: Y:\MIS_DATABASE\Library\ALTIUM_TOOL\PCB_FOOTPRINTS\Altium_Footprint_Lib.PcbLib; Height: 0.28MM; Library Path: Y:\MIS_DATABASE\Library\ALTIUM_TOOL\SCHEMATICS_PARTS\MS_DISCRETE_Library.schlib; Mfr_name: VISHAY; Mfr_part_number: CRCW020110K0FNED; Mistral Part No: 110018060032-R; Package: 0201; Part_type: RESISTORS\FIXED; Project: NEXTNAV_LPRX_BOARD; RoHS: RoHS; Temperature: -55°C+155°C; Tolerance: 1%; Voltage: NA; Wattage: 1/20W; Weight: 0.17mg; Datasheet: Y:\MIS_DATABASE\DATASHEETS\RESISTORS\CRCW0201.PDF
R449 = RESISTOR: RES 1M 1/16W 1% 0402; Chkd/date: MANIRAJA/190319; Crtd /date: MANIRAJA/190319; Custom_Duty: 15%; Customs_HS_Code: 85332119; Distributor_name: DIGIKEY; Distributor_part_number: 311-1.00MLRCT-ND; Footprint Path: Y:\MIS_DATABASE\Library\ALTIUM_TOOL\PCB_FOOTPRINTS\Altium_Footprint_Lib.PcbLib; Height: 0.40MM; Library Path: Y:\MIS_DATABASE\Library\ALTIUM_TOOL\SCHEMATICS_PARTS\MS_DISCRETE_Library.schlib; Mfr_name: YAGEO AMERICA; Mfr_part_number: RC0402FR-071ML; Mistral Part No: 110014060045-R; Package: 0402; Part_type: RESISTORS\FIXED; Project: G4SLIM; RoHS: RoHS; Temperature: -55°C+155°C; Tolerance: 1%; Voltage: NA; Wattage: 1/16W; Weight: 0.65mg; Datasheet: Y:\MIS_DATABASE\DATASHEETS\RESISTORS\RCXXXXL-SER_MAR18.PDF
R465 R471 R497 = RESISTOR: RES 100K 1/10W 1% 0402; Chkd/date: VASANTHA/201216; Crtd /date: MAZHAR/130306; Custom_Duty: 15%; Customs_HS_Code: 85332119; Distributor_name: DIGIKEY; Distributor_part_number: P100KLCT-ND; Footprint Path: Y:\MIS_DATABASE\Library\ALTIUM_TOOL\PCB_FOOTPRINTS\Altium_Footprint_Lib.PcbLib; Height: 0.40MM; Library Path: Y:\MIS_DATABASE\Library\ALTIUM_TOOL\SCHEMATICS_PARTS\MS_DISCRETE_Library.schlib; Mfr_name: PANASONIC-ECG; Mfr_part_number: ERJ-2RKF1003X; Mistral Part No: 110009030187-R; Package: 0402; Part_type: RESISTORS\FIXED; Project: J32; RoHS: RoHS; Temperature: -55°C+155°C; Tolerance: 1%; Voltage: NA; Wattage: 1/10W; Weight: 0.8mg; Datasheet: Y:\MIS_DATABASE\DATASHEETS\RESISTORS\PAN-ERJSER_NOV17.PDF
R466 = RESISTOR: RES 0E 1/20W JUMPER 0201; Chkd/date: VASANTHA/061216; Crtd /date: MAZHAR/040505; Custom_Duty: 15%; Customs_HS_Code: 85332119; Distributor_name: DIGIKEY; Distributor_part_number: P0.0AGCT-ND; Footprint Path: Y:\MIS_DATABASE\Library\ALTIUM_TOOL\PCB_FOOTPRINTS\Altium_Footprint_Lib.PcbLib; Height: 0.26MM; Library Path: Y:\MIS_DATABASE\Library\ALTIUM_TOOL\SCHEMATICS_PARTS\MS_DISCRETE_Library.schlib; Mfr_name: PANASONIC-ECG; Mfr_part_number: ERJ-1GE0R00C; Mistral Part No: 110009030078-R; Package: 0201; Part_type: RESISTORS\FIXED; Project: HS100RD; RoHS: RoHS; Temperature: -55°C+125°C; Tolerance: NA; Voltage: NA; Wattage: 1/20W; Weight: 0.15mg; Datasheet: Y:\MIS_DATABASE\DATASHEETS\RESISTORS\PAN-ERJXGE-FEB06.PDF
R470 R495 R502 = RESISTOR: RES 10K 1/20W 1% 0201; Chkd/date: VASANTHA/270117; Crtd /date: MANIRAJA/270117; Custom_Duty: 15%; Customs_HS_Code: 85332119; Distributor_name: DIGIKEY; Distributor_part_number: 311-10.0KMCT-ND; Footprint Path: Y:\MIS_DATABASE\Library\ALTIUM_TOOL\PCB_FOOTPRINTS\Altium_Footprint_Lib.PcbLib; Height: 0.26MM; Library Path: Y:\MIS_DATABASE\Library\ALTIUM_TOOL\SCHEMATICS_PARTS\MS_DISCRETE_Library.schlib; Mfr_name: YAGEO AMERICA; Mfr_part_number: RC0201FR-0710KL; Mistral Part No: 110011040018-R; Package: 0201; Part_type: RESISTORS\FIXED; Project: GOLDEN-I LITE; RoHS: RoHS; Temperature: -55°C+125°C; Tolerance: 1%; Voltage: NA; Wattage: 1/20W; Weight: 0.17mg; Datasheet: Y:\MIS_DATABASE\DATASHEETS\RESISTORS\RCXXXXL-SER_MAR18.PDF
R483 = RESISTOR: RES 0E 1/16W JUMPER 0402; Chkd/date: VASANTHA/201216; Crtd /date: MUDDU/190810; Custom_Duty: 15%; Customs_HS_Code: 85332119; Distributor_name: DIGIKEY; Distributor_part_number: 541-0.0JCT-ND; Footprint Path: Y:\MIS_DATABASE\Library\ALTIUM_TOOL\PCB_FOOTPRINTS\Altium_Footprint_Lib.PcbLib; Height: 0.40MM; Library Path: Y:\MIS_DATABASE\Library\ALTIUM_TOOL\SCHEMATICS_PARTS\MS_DISCRETE_Library.schlib; Mfr_name: VISHAY; Mfr_part_number: CRCW04020000Z0ED; Mistral Part No: 110010080019-R; Package: 0402; Part_type: RESISTORS\FIXED; Project: PB_BUGBASE; RoHS: RoHS; Temperature: -55°C+155°C; Tolerance: NA; Voltage: NA; Wattage: 1/16W; Weight: 0.65mg; Datasheet: Y:\MIS_DATABASE\DATASHEETS\RESISTORS\CRCW0603.PDF
R484 = RESISTOR: RES 100K 1/20W 5% 0201; Chkd/date: VASANTHA/061216; Crtd /date: MAZHAR/141105; Custom_Duty: 15%; Customs_HS_Code: 85332119; Distributor_name: DIGIKEY; Distributor_part_number: P100KAGCT-ND; Footprint Path: Y:\MIS_DATABASE\Library\ALTIUM_TOOL\PCB_FOOTPRINTS\Altium_Footprint_Lib.PcbLib; Height: 0.26MM; Library Path: Y:\MIS_DATABASE\Library\ALTIUM_TOOL\SCHEMATICS_PARTS\MS_DISCRETE_Library.schlib; Mfr_name: PANASONIC-ECG; Mfr_part_number: ERJ-1GEJ104C; Mistral Part No: 110009030176-R; Package: 0201; Part_type: RESISTORS\FIXED; Project: J30; RoHS: RoHS; Temperature: -55°C+125°C; Tolerance: 5%; Voltage: NA; Wattage: 1/20W; Weight: 0.15mg; Datasheet: Y:\MIS_DATABASE\DATASHEETS\RESISTORS\PAN-ERJXGE-FEB06.PDF
TP92 = TESTPOINT: TESTPOINT CIR 20 SMD; Chkd/date: SHREESHAIL/171006; Crtd /date: MAZHAR/171006; Custom_Duty: NA; Customs_HS_Code: NA; Distributor_name: NA; Distributor_part_number: NA; Footprint Path: Y:\MIS_DATABASE\Library\ALTIUM_TOOL\PCB_FOOTPRINTS\Altium_Footprint_Lib.PcbLib; Height: NA; Library Path: Y:\MIS_DATABASE\Library\ALTIUM_TOOL\SCHEMATICS_PARTS\MS_DISCRETE_Library.schlib; MECHANICAL 3D STEP FILE: NA; Mfr_name: LOCAL; Mistral Part No: NA; Package: SMD; Project: BT MODULE_CSRBC04; RoHS: NA; Temperature: NA; Tolerance: NA; Voltage: NA; Wattage: NA; Weight: NA; Datasheet: NA
U39 = W25Q80BWSNIG_SOIC8: IC SERIAL FLASH MEMORY SOIC8; Chkd/date: VASANTHA/150217; Crtd /date: MANIRAJA/150217; Custom_Duty: 15%; Customs_HS_Code: 85423100; Distributor_name: DIGIKEY; Distributor_part_number: W25Q80DVSNIG CT-ND; Height: 1.75MM; Mfr_name: WINBOND; Mfr_part_number: W25Q80DVSNIG-TR; Mistral Part No: 141117020010-R; Package: SOIC8; Part_type: ICS\DIGITAL\MEMORY; Project: SD820_NANO_SOM; RoHS: RoHS; Temperature: -40°C+85°C; Tolerance: NA; Voltage: NA; Wattage: NA; Weight: NA; Datasheet: Y:\MIS_DATABASE\DATASHEETS\ICS\MEMORY\W25Q80DVSS.PDF
U68 = TPS65988DJ_VQFN56: IC 2-PORT USB TYPE-C AND USB PD CONTROLLER WITH INTEGRATED POWER SWITCH VQFN56; Chkd/date: MANIRAJA/290721; Crtd /date: ALVY/280721; Custom_Duty: 15%; Customs_HS_Code: 85423100; Distributor_name: DIGIKEY; Distributor_part_number: 296-52068-1-ND; Footprint Path: Y:\MIS_DATABASE\Library\ALTIUM_TOOL\PCB_FOOTPRINTS\Altium_Footprint_Lib.PcbLib; Height: 1.00MM; Library Path: Y:\MIS_DATABASE\Library\ALTIUM_TOOL\SCHEMATICS_PARTS\MS_MISCPOWER_Library.schlib; Mfr_name: TEXAS INSTRUMENTS; Mistral Part No: 142021070017-R; Package: VQFN56; Part_type: ICS\POWER\MANAGEMENT; Project: TI_AM62x_SKEVM; RoHS: RoHS; Temperature: -10°C+75°C; Tolerance: NA; Voltage: NA; Wattage: NA; Weight: 127.6mg; Datasheet: Y:\MIS_DATABASE\DATASHEETS\ICS\POWER\TPS65988DHRSHR.PDF
U69 = TVS2200_WSON6: IC 22V FLAT-CLAMP SURGE PROTECTION DEVICE WSON6; Chkd/date: MANIRAJA/011021; Crtd /date: ALVY/011021; Custom_Duty: 15%; Customs_HS_Code: 85423100; Distributor_name: DIGIKEY; Distributor_part_number: 296-52187-1-ND; Footprint Path: Y:\MIS_DATABASE\Library\ALTIUM_TOOL\PCB_FOOTPRINTS\Altium_Footprint_Lib.PcbLib; Height: 0.80MM; Library Path: Y:\MIS_DATABASE\Library\ALTIUM_TOOL\SCHEMATICS_PARTS\MS_MISCPOWER_Library.schlib; Mfr_name: TEXAS INSTRUMENTS; Mistral Part No: 142021100001-R; Package: WSON6; Part_type: ICS\POWER; Project: TI_AM62x SKEVM_BRD; RoHS: RoHS; Temperature: -40°C+125°C; Tolerance: NA; Voltage: NA; Wattage: NA; Weight: 12mg; Datasheet: Y:\MIS_DATABASE\DATASHEETS\ICS\POWER\TVS2200.PDF
C510-C516 = CAP: CAP CERAMIC 0.1uF 16V 10% X5R 0201; Alt_Mfr_name: YAGEO AMERICA; Alt_Mfr_part_number: CC0402KRX5R8BB104; Chkd/date: MANIRAJA/230118; Crtd /date: MANIRAJA/230118; Custom_Duty: 15%; Customs_HS_Code: 85322990; Distributor_name: DIGIKEY; Distributor_part_number: 490-14305-1-ND; Footprint Path: Y:\MIS_DATABASE\Library\ALTIUM_TOOL\PCB_FOOTPRINTS\Altium_Footprint_Lib.PcbLib; Height: 0.33MM; Library Path: Y:\MIS_DATABASE\Library\ALTIUM_TOOL\SCHEMATICS_PARTS\MS_DISCRETE_Library.schlib; Mfr_name: MURATA; Mfr_part_number: GRM033R61C104KE14D; Mistral Part No: 120009030072-R; Package: 0201; Part_type: CAPACITORS\CERAMIC; Project: TI_MAXIE_CPB; RoHS: RoHS; Temperature: -55°C+85°C; Tolerance: 10%; Voltage: 16V; Wattage: NA; Weight: 0.33mg; Datasheet: Y:\MIS_DATABASE\DATASHEETS\CAPACITORS\GRM033R61C104KE14.PDF
R686 R687 R689 R690 = RESISTOR: RES 4.7K 1/20W 5% 0201; Chkd/date: MANIRAJA/200921; Crtd /date: ALVY/200921; Custom_Duty: 15%; Customs_HS_Code: 85332119; Distributor_name: DIGIKEY; Distributor_part_number: 311-4.7KNCT-ND; Footprint Path: Y:\MIS_DATABASE\Library\ALTIUM_TOOL\PCB_FOOTPRINTS\Altium_Footprint_Lib.PcbLib; Height: 0.26MM; Library Path: Y:\MIS_DATABASE\Library\ALTIUM_TOOL\SCHEMATICS_PARTS\MS_DISCRETE_Library.schlib; Mfr_name: YAGEO AMERICA; Mfr_part_number: RC0201JR-074K7L; Mistral Part No: 110021090007-R; Package: 0201; Part_type: RESISTORS\FIXED; Project: TI_AM62x SKEVM_BRD; RoHS: RoHS; Temperature: -55°C+125°C; Tolerance: 5%; Voltage: NA; Wattage: 1/20W; Weight: 0.17mg; Datasheet: Y:\MIS_DATABASE\DATASHEETS\RESISTORS\RCXXXXL-SER_MAR18.PDF
U106 U107 = TCA9517DGKR_VSSOP8: IC 2-CHANNEL BI-DIR LEVEL-SHIFTING I2C BUS REPEATER SOIC8; Chkd/date: MANIRAJA/171121; Crtd /date: ALVY/161121; Custom_Duty: 15%; Customs_HS_Code: 85423100; Distributor_name: DIGIKEY; Distributor_part_number: 296-39221-1-ND; Footprint Path: Y:\MIS_DATABASE\Library\ALTIUM_TOOL\PCB_FOOTPRINTS\Altium_Footprint_Lib.PcbLib; Height: 1.75MM; Library Path: Y:\MIS_DATABASE\Library\ALTIUM_TOOL\SCHEMATICS_PARTS\MS_MISCINTERFACE_Library.schlib; Mfr_name: TEXAS INSTRUMENTS; Mistral Part No: 141021110017-R; Package: SOIC8; Part_type: ICS\INTERFACE\LEVEL TRANSLATOR; Project: EXCITER MULTI-CH RX UNIT; RoHS: RoHS; Temperature: -40°C+85°C; Tolerance: NA; Voltage: NA; Wattage: NA; Weight: 540mg; Datasheet: Y:\MIS_DATABASE\DATASHEETS\ICS\INTERFACE\TCA9517.PDF
U108 = 74HC7014X_SOIC14: IC HEX BUFFER AND DRIVER WITH OPEN DRAIN OUTPUT TVSOP14; Chkd/date: ALVY/070422; Crtd /date: TAMILARASU/070422; Custom_Duty: 15%; Customs_HS_Code: 85423100; Distributor_name: DIGIKEY; Distributor_part_number: 296-8440-1-ND; Footprint Path: Y:\MIS_DATABASE\Library\ALTIUM_TOOL\PCB_FOOTPRINTS\Altium_Footprint_Lib.PcbLib; Height: 1.20MM; Library Path: Y:\MIS_DATABASE\Library\ALTIUM_TOOL\SCHEMATICS_PARTS\MS_COMBINATIONAL_Library.schlib; Mfr_name: TEXAS INSTRUMENTS; Mistral Part No: 141022040005-R; Package: TVSOP14; Part_type: ICS\DIGITAL\COMBINATIONAL; Project: TI_AM62x_SKEVM_BRD; RoHS: RoHS; Temperature: -40°C+125°C; Tolerance: NA; Voltage: NA; Wattage: NA; Weight: 41.8mg; Datasheet: Y:\MIS_DATABASE\DATASHEETS\ICS\DIGITAL\COMBINATIONAL\SN74LVC07A.PDF
U109 = TXS0102DQX_SON8: IC 2-BIT BI-DIR VOLTAGE-LEVEL TRANSLATOR FOR OPEN-DRAIN AND PUSH-PULL X2SON8; Chkd/date: MANIRAJA/010719; Crtd /date: CHAITHANYA230512; Custom_Duty: 15%; Customs_HS_Code: 85423100; Distributor_name: DIGIKEY; Distributor_part_number: 296-28368-1-ND; Footprint Path: Y:\MIS_DATABASE\Library\ALTIUM_TOOL\PCB_FOOTPRINTS\Altium_Footprint_Lib.PcbLib; Height: 0.40MM; Library Path: Y:\MIS_DATABASE\Library\ALTIUM_TOOL\SCHEMATICS_PARTS\MS_MISCINTERFACE_Library.schlib; Mfr_name: TEXAS INSTRUMENTS; Mistral Part No: 141012050010-R; Package: X2SON8; Part_type: ICS\INTERFACE\LEVEL TRANSLATOR; Project: GEN_3-8_DB; RoHS: RoHS; Temperature: -40°C+85°C; Tolerance: NA; Voltage: NA; Wattage: NA; Weight: 1.2mg; Datasheet: Y:\MIS_DATABASE\DATASHEETS\ICS\INTERFACE\TXS0102-SER.PDF

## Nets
DGND: C134.2 C135.2 C136.2 C138.2 C139.2 C141.2 C142.1 C143.2 C144.1 C147.2 C150.2 C151.2 C152.2 C153.2 C392.2 C398.2 C401.2 C409.2 C415.2 C423.2 C432.2 C433.2 C510.1 C511.1 C512.1 C513.1 C514.2 C515.2 C516.2 C517.2 C518.2 D2.2(ANODE) D9.2(ANODE) J11.A1(GND) J11.A12(GND) J11.B1(GND) J11.B12(GND) J22.2 J22.10 LD10.1(CATHODE) Q13.4(S1) Q13.7(S2) R178.2 R449.1 R465.2 R471.2 R484.2 R497.2 R685.1 R688.1 R691.1 U39.4(GND) U68.20(GND) U68.51(GND) U68.59(GND) U69.1(GND) U69.2(GND) U69.3(GND) U69.7(GND) U106.4(GND) U107.4(GND) U108.7(GND) U109.3(A2) U109.4(GND) U109.6(B2) ; also on sheet 11 12 13 14 15 16 17 18 19 20 21 22 23 24 25 26 27 28 29 30 31 32 33 34 35 36 37 38 39 40 41 42 43
VBUS_TYPEC1: C139.1 C398.1 C401.1 J11.A4(VBUS1) J11.A9(VBUS2) J11.B4(VBUS3) J11.B9(VBUS4) R182.1 U68.13(VBUS1) U69.4(IN1) U69.5(IN2) U69.6(IN3)
VBUS_TYPEC2: C147.1 C409.1 C415.1 C432.1 C433.1 C435.1 Q16.4(D1) Q16.7(D2) R515.1 U68.3(VBUS2) ; also on sheet 35 36
VCC3V3_TA: C511.2 C513.2 C516.1 R693.2 R694.2 U106.8(VCCB) U107.8(VCCB) U109.8(VCCB) ; also on sheet 26 27
VCC3V3_XDS: C510.2 C512.2 C514.1 C515.1 R686.1 R687.1 R689.1 R690.1 R692.2 U106.1(VCCA) U107.1(VCCA) U108.14(VCC) U109.1(VCCA) ; also on sheet 28 29
VCC_3V3_SYS: R696.1 ; also on sheet 12 13 14 18 19 20 22 23 24 25 26 27 29 30 31 32 33 34 35 36 37 38 39 40 41 42 43
VCC_5V0: C161.1 C423.1 C517.1 C518.1 Q14.4(D1) Q14.7(D2) R223.1 R483.1 ; also on sheet 11 33 36 41
ADCIN1: R470.2 R471.1 U68.6(ADCIN1)
ADCIN2: R465.1 R466.2 U68.10(ADCIN2)
BOOTMODE_I2C_EN: R688.2 R694.1 U107.5(EN)
BOOTMODE_I2C_SCL: R598.2 ; also on sheet 26 27
BOOTMODE_I2C_SDA: R580.2 ; also on sheet 26 27
BOOTMODE_XDS_I2C_SCL: R690.2 U107.2(SCLA) ; also on sheet 28
BOOTMODE_XDS_I2C_SDA: R689.2 U107.3(SDAA) ; also on sheet 28
DRAIN1: U68.8(DRAIN1_1) U68.15(DRAIN1_2) U68.19(DRAIN1_3) U68.58(DRAIN1_4)
DRAIN2: U68.7(DRAIN2_1) U68.52(DRAIN2_2) U68.56(DRAIN2_3) U68.57(DRAIN2_4)
LDO_1V8: C143.1 U68.35(LDO_1V8)
LDO_3V3: C134.1 C142.2 R177.1 R179.1 R180.1 R181.1 R184.1 R185.1 R450.1 R451.1 R452.1 R457.1 R466.1 R470.1 U39.8(VCC) U68.9(LDO_3V3)
P2_PP_EXT_ENABLE: R494.1 U68.49(GPIO17/PP_EXT2)
PD_GPIO0: R625.2 U68.16(GPIO0)
PD_GPIO2: TP92.1(TP) U68.18(GPIO2)
PD_HRESET: R484.1 U68.44(HRESET)
PD_I2C_IRQ: R695.1 R696.2 ; also on sheet 39
PD_M_I2C3_IRQ: R450.2 U68.23(~{I2C3_IRQ}/GPIO7)
PD_M_I2C3_SCL: R158.1 R184.2 U68.21(I2C3_SCL/GPIO5)
PD_M_I2C3_SDA: R164.1 R181.2 U68.22(I2C3_SDA/GPIO6)
PD_MS_I2C1_IRQ: R457.2 U68.29(~{I2C1_IRQ})
PD_MS_I2C1_SCL: R157.1 R452.2 U68.27(I2C1_SCL)
PD_MS_I2C1_SDA: R163.1 R451.2 U68.28(I2C1_SDA)
PD_S_I2C2_IRQ: R695.2 U68.34(~{I2C2_IRQ})
PD_S_I2C2_SCL: R460.2 U68.32(I2C2_SCL)
PD_S_I2C2_SDA: R464.2 U68.33(I2C2_SDA)
PD_SPI_CLK: J22.7 R478.2 U39.6(CLK)
PD_SPI_MISO: J22.5 R179.2 R468.2 U39.2(DO(IO1))
PD_SPI_MOSI: J22.8 R473.2 U39.5(DI(IO0))
PD_SPI_SS: J22.9 R177.2 R480.2 U39.1(~{CS})
PD_VIN_3V3: C144.2 U68.5(VIN_3V3)
PP1_CABLE: C138.1 U68.25(PP1_CABLE)
PP2_CABLE: R483.2 U68.46(PP2_CABLE)
SoC_I2C0_SCL: R460.1 ; also on sheet 13 22 32 33 37 42
SoC_I2C0_SDA: R464.1 ; also on sheet 13 22 32 33 37 42
SoC_I2C1_TA_SCL: R544.2 ; also on sheet 26
SoC_I2C1_TA_SDA: R525.2 ; also on sheet 26
SoC_I2C1_XDS_SCL: R686.2 U106.2(SCLA) ; also on sheet 28
SoC_I2C1_XDS_SDA: R687.2 U106.3(SDAA) ; also on sheet 28
SoC_USB0_DRVVBUS: R492.1 R625.1 ; also on sheet 36
SPI_HOLDn: R180.2 U39.7(~{HOLD}(IO3))
SPI_WPn: R185.2 U39.3(~{WP}(IO2))
TEST_GPIO1: R225.2 ; also on sheet 26 43
TEST_GPIO1_XDS: U108.1(1A) ; also on sheet 28
TEST_GPIO2: R231.2 ; also on sheet 26
TEST_GPIO2_XDS: U109.2(A1) ; also on sheet 28
TEST_GPIO3: R226.2 ; also on sheet 26 27
TEST_GPIO3_XDS: U108.3(2A) ; also on sheet 28
TEST_GPIO4: R232.2 ; also on sheet 26 27
TEST_GPIO4_XDS: U108.5(3A) ; also on sheet 28
TEST_PORZn: R224.2 ; also on sheet 26 42
TEST_PORZn_XDS: U108.9(4A) ; also on sheet 28
TEST_POWERDOWN: R229.2 ; also on sheet 13 26
TEST_POWERDOWN_XDS: U108.13(6A) ; also on sheet 28
TEST_WARMRESETn: R230.2 ; also on sheet 26 43
TEST_WARMRESETn_XDS: U108.11(5A) ; also on sheet 28
USB_TYPEC1_EARTH: C392.1 J11.SH1 J11.SH2 J11.SH3 J11.SH4 R178.1
USBC_CONN1_CC1: C136.1 D2.1(CATHODE) J11.A5(CC1) U68.24(C1_CC1)
USBC_CONN1_CC2: C135.1 D9.1(CATHODE) J11.B5(CC2) U68.26(C1_CC2)
USBC_CONN2_CC1: C152.1 U68.45(C2_CC1) ; also on sheet 35
USBC_CONN2_CC2: C151.1 U68.47(C2_CC2) ; also on sheet 35
VMAIN: C141.1 C150.1 C153.1 U68.1(PP_HV2) U68.11(PP_HV1) ; also on sheet 11 12
XDS_I2C1_EN: R685.2 R693.1 U106.5(EN)
N17029933: LD10.2(ANODE) R182.2
N17370891: R449.2 U68.17(GPIO1)
N17824845: R468.1 U68.36(SPI_MISO/GPIO8)
N17824852: R473.1 U68.37(SPI_MOSI/GPIO9)
N17824859: R478.1 U68.38(SPI_CLK/GPIO10)
N17824866: R480.1 U68.39(~{SPI_SS}/GPIO11)
N17827086: J22.1 R157.2 R158.2
N17827089: J22.3 R163.2 R164.2
N17849698: C162.1 Q14.1(S1) Q14.2(S2) Q14.5(S3) Q14.6(S4) Q14.8(S5) Q16.1(S1) Q16.2(S2) Q16.5(S3) Q16.6(S4) Q16.8(S5) R495.1
N17850096: C161.2 C162.2 C435.2 Q14.3(G) Q16.3(G) R223.2 R495.2 R502.1 R515.2
N17935978: Q13.3(G) R492.2 R494.2 R497.1
N17936309: Q13.1(D1) Q13.2(D2) Q13.5(D3) Q13.6(D4) Q13.8(D5) R502.2
N20501313: R231.1 U109.7(B1)
N20503848: R691.2 R692.1 U109.5(OE)
N20547674: R225.1 U108.2(1Y)
N20547852: R226.1 U108.4(2Y)
N20548002: R232.1 U108.6(3Y)
N20548130: R224.1 U108.8(4Y)
N20548208: R230.1 U108.10(5Y)
N20548250: R229.1 U108.12(6Y)
N20610314: R544.1 U106.7(SCLB)
N20610315: R525.1 U106.6(SDAB)
N20611580: R598.1 U107.7(SCLB)
N20611582: R580.1 U107.6(SDAB)

Not connected (* = marked no-connect by the designer): J11 A2(TX1+)* A3(TX1-)* A6(D+_1)* A7(D-_1)* A8(SBU1)* A10(RX2-)* A11(RX2+)* B2(TX2+)* B3(TX2-)* B6(D+_2)* B7(D-_2)* B8(SBU2)* B10(RX1-)* B11(RX1+)*; J22 4* 6*; U68 30(HPD1/GPIO3)* 31(HPD2/GPIO4)* 40(GPIO12)* 41(GPIO13)* 42(GPIO14/PWM)* 43(GPIO15/PWM)* 48(GPIO16/PP_EXT1)* 50(C1_USB_P/GPIO18)* 53(C1_USB_N/GPIO19)* 54(C2_USB_P/GPIO20)* 55(C2_USB_N/GPIO21)*

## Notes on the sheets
sheet 1
- I2C_TA BUS BUFFER
- BOOTMODE_I2C_TA BUFFER
- ISOLATION BUFFERS FOR TA SIGNALS
- Pull ups(R567, R587, R517, R568, R585, R586 & R566) to
  VCC3V3_TA are present
sheet 2
- AM625 / AM623 Starter Kit SK (EVM) WITH TPS6521904 PMIC
- TABLE OF CONTENTS
- Revision Number
- PAGE
- CONTENTS
- PAGE
- CONTENTS
- REV
- A1
- 01
- TABLE OF CONTENTS
- 23
- CPSW3G RGMII_2 ETHERNET PHY
- VER
- 0.12
- 02
- REVISION HISTORY
- 24
- SOC MAC INTRFACE, SOC AND ETHERNET PHYs CLOCK BUFFER, LED DRIVER
- 03
- BLOCK DIAGRAM FOR AM625 / AM623 STARTER KIT SK (EVM)
- 25
- TEST AUTOMATION
- 04
- BLOCK DIAGRAM XDS110 DEBUGGER
- 26
- BOOT MODE CONFIGURATION BUFFERS, RESISTOR DIVIDERS & DIP SWITCHES
- 05
- POWER ARCHITECTURE BLOCK DIAGRAM
- 27
- XDS110 DEBUGGER
- 06
- POWER-UP AND POWER-DOWN SEQUENCE
- 28
- AUTOMATION SIGNALS BUFFER
- 07
- I2C TREE
- 29
- SOC JTAG INTERFACE AND JTAG BUFFERS
- 08
- GPIO MAPPING TABLE
- 30
- JTAG 20 PIN cTI CONNECTOR AND BUFFERS
- 09
- USB TYPE-C PD CONTROLLER AND POWER SUPPLY
- 31
- FT4232 UART TO USB BRIDGE
- 10
- PERIPHERAL POWER SUPPLIES-1
- 32
- SOC LFOSC0 AND SOC BOOTMODE INPUT PINS, PRU HEADER
- 11
- PERIPHERAL POWER SUPPLIES-2
- 33
- USER EXPANSION CONNECTOR
- 12
- SOC POWER SUPPLIES - USING PMIC
- 34
- SOC-MCU DOMAIN IO, OSC0 AND SOC-MCU IO HEADER
- 13
- SOC SUPPLY RAILS CURRENT MONITORING
- 35
- USB0 TYPE-C DRP
- 14
- SOC SUPPLY RAILS AND POWER SUPPLIES
- 36
- SOC USB INTERFACE, USB1 TYPE-A CONNECTOR, VBUS DIVIDER & POWER SWITCH
- 15
- CAPS FOR SOC POWER SUPPLIES AND SOC GROUND VSS
- 37
- SOC OLDI INTERFACE, LCD CONNECTOR AND SOC UART1 FET SWITCH & BUFFER
- 16
- SOC DDRSS AND DDR4 MEMORY DEVICE INTERFACE
- 38
- SOC CSI INTERFACE AND CAMERA CONNECTOR
- 17
- M.2 INTERFACE AND CONNECTOR
- 39
- IO EXPANDER AND MCASP1 FET SWITCH & BUFFER
- 18
- SOC MMC0.2 INTERFACE AND eMMC FLASH + RESET
- 40
- AUDIO CODEC
- 19
- SD CARD - LOAD SWITCH, LOAD SWITCH RESET LOGIC AND DATA INTERFACE
- 41
- SOC DPI INTERFACE, DPI TO HDMI TRANSMITTER INTERFACE
- 20
- SOC OSPI/QSPI INTERFACE AND OSPI FLASH
- 42
- SOC RESET AND IOs, AND EXTERNAL LVCMOS CLOCK (OSCILLATOR)
- 21
- BOARD ID EEPROM & DIGITAL TEMPERATURE SENSORS
- 43
- SOC PUSH BUTTON RESET INPUTS, DEBOUNCE LOGIC FOR RC RESET
- 22
- CPSW3G RGMII_1 ETHERNET PHY
- 44
- ASSEMBLY NOTES AND MOUNTING HARDWARE
- D-Note :-
- SK/EVM is a device evaluation board or platform. The SK/EVM is not a reference design. In some cases the EVM implementation may deviate from
  the optimum solution to provide a better customer experience or provide flexibility for customers to be able to validate the SOC functionality.
  TI expects and recommends customers to carefully review and follow all requirements defined in the datasheet, silicon errata, and TRM when
  designing their custom board. The information found in the datasheet should always take precedence over the SK/EVM implementation.
- R-Note:-
- * Verify the DNI components configuration with respect to the SK schematics (Use PDF) after completion of board design before board assembly
  * A standard 5% tolerance resistor can be used for most of the series and parallel pull resistor
  * Be sure to read through all the D-Notes (Design notes), R-Notes (Review notes) and CAD notes during board design and before start of
  board build.  (Refer FAQs listed for additional details)
- KEY LINKS TO COLLATERALS
- Hardware Design Guide :
- https://www.ti.com/lit/an/sprad05b/sprad05b.pdf
- Schematic Design and Review Checklist :
- https://www.ti.com/lit/an/sprad21d/sprad21d.pdf
- PMIC Power Solutions application note :
- https://www.ti.com/lit/an/slvafd0b/slvafd0b.pdf
- DDR Board Design and Layout Guidelines :
- https://www.ti.com/lit/an/sprad06/sprad06.pdf
- SKs (Starter Kits) for reference :
- SK-AM62B, SK-AM62B-P1, SK-AM62-LP, SK-AM62-SIP, SK-AM62A-LP, SK-AM62P-LP
sheet 3
- REVISION HISTORY
- VER #
- DATE
- DESCRIPTION OF CHANGES
- AUTHOR
- REVIEWED  BY
- APPROVED  BY
- 0.01
- 29 AUG 2022
- Drafted from PROC142E1 Schematics. R651 value changed to 1K. DNI'd R618 and R676.Changed the
  I2C buffer parts to TCA9517DR. Changed the part SN74AVC4T245RSVR to SN74AVC4T245DGVR
- Mistral Design Team
- 0.02
- Added the second GPIO Expander U110 Part# TCA6408ARGTR
- Mistral Design Team
- 08 SEP 2022
- 0.03
- Changed the Current monitors Res Filter values from 10E to 0E to the Sense pins.
- Mistral Design Team
- 21 SEP 2022
- 0.04
- Added Testpoint to TEMP_DIODE_P pin of SoC.
  Changed the GPIO_OLDI_RSTn net name to GPIO_TS_RSTn.
- Mistral Design Team
- 19 OCT 2022
- Changed the PMIC part from TPS6521903RHBR to TPS6521904RHBR. Mounted R699 and
  DNI'd R123. DNI'd the current monitor section of U36
- 0.05
- 24 OCT 2022
- Mistral Design Team
- Changed the DDR4 part from MT40A1G16KD-062E IT:E to MT40A1G16TB-062E IT:F.
  Changed the eMMC part from MTFC16GAPALBH-IT to MTFC32GAZAQHD-IT.
- 0.06
- 3 Nov 2022
- Mistral Design Team
- 0.07
- Removed the PMIC_STBY connection from SOC to PMIC.
- Mistral Design Team
- 15 Nov 2022
- 0.08
- Added 2x 47uF on VCC_5V0. DNI'd C432, C433(10uF) and changed C415 to 4.7uF. Added
  22pF CAP across R108
- Mistral Design Team
- 22 Nov 2022
- 0.09
- Removed MMC2 connector section (J18) and associated resistors
- 1 Dec 2022
- Mistral Design Team
- Changed the HDMI external swing resistance to 7.5K. Added Standoff,Screw & Washer
  for M.2 connector. DNI'd R650 on SoC_USB1_DRVVBUS
- 11 APR 2023
- 0.10
- Mistral Design Team
- 0.11
- 16 MAY 2023
- Depopulated Pull up of SOC_WLAN_IRQ_1V8 (R6)
- Mistral Design Team
- Updated SoC Part Number, Enabled Voltage ratings for all the capacitors and added
  Design Review notes
- Moved to DNI : R222, R650, C305, C303, C156, Q2,  Y4
- Moved to Mount : R319, R309, R318, R310, R306, R307, R308, R303, R538, R572
- 0.12
- 27 MAY 2024
- C86 - 1uF changed to 2.2uF ; C60 - 4.7uF changed to 1uF ; C46 - 0.1uF changed to 4.7uF ;
  C47,C387,C194,C12 - 1uF changed to 0.1uF ; C77, C33 - 4.7uF changed to 10uF ; C75,C79 -
  9pF changed to 18pF ; C391,C14,C193 - 2.2uF changed to 1uF
- Mistral Design Team
- R651 - 1K_0.1% changed to Std 1K ; R404,R408 - 1K_0.1% changed to 1K_1% ;
  R89,R353,R354,R301,R302 - 22E_1% changed to 0E ; R12,R333,R398 - 49.9K_1% changed to Std 10K ;
  R393,R475 - 10K_1% changed to Std 10K; R315 - 100K changed to 10k; R56 - 0E changed to Std 22E.
- LINKS TO KEY FAQs
- https://e2e.ti.com/support/processors-group/processors/f/processors-forum/1183910/faq-am625-custom-board-hardware-design-collaterals-to-get-started
- https://e2e.ti.com/support/processors-group/processors/f/processors-forum/1184006/faq-am623-custom-board-hardware-design-collaterals-to-get-started
- https://e2e.ti.com/support/processors-group/processors/f/processors-forum/1285107/faq-am64x-am62x-am62ax-am62px-custom-board-hardware-design---
  collaterals-for-reference-during-schematic-design-and-schematics-review
- https://e2e.ti.com/support/processors-group/processors/f/processors-forum/1280721/faq-am625-am623-am625sip-am625-q1-am620-q1-custom-board-hardware-
  design---faqs-related-to-processor-collaterals-functioning-peripherals-interface-and-starter-kit
- https://e2e.ti.com/support/processors-group/processors/f/processors-forum/1332316/faq-am625-am623-custom-board-hardware-design---design-and-
  review-notes-for-reuse-of-sk-am62b-p1-schematics
sheet 4
- BLOCK DIAGRAM
sheet 5
- BLOCK DIAGRAM_XDS110
- D-Note:-
- Please follow SK-AM62P-LP  implementations for latest updates on XDS110
sheet 6
- POWER BLOCK DIAGRAM
sheet 7
- POWER SEQUENCE
sheet 8
- I2C TREE
- R-Note
  Refer below section of the data sheet
  Timing and Switching Characteristics
  I2C Exceptions
- R-Note
  Add - Indicates Address
- R-Note:-
- For all emulated open-drain output LVCMOS I2C interfaces.
   (I2C0, I2C1, I2C2, I2C3) pullup resistors are recommended
  The IOs associated with these ports are not compliant to the
  fall time requirements defined in the I2C specification.
  Location of the pullup is not a concern.
  It is recommended to connect the pullups with the shortest
  possible stub
- R-Note:-
- For I2C interfaces with open-drain output type buffer (MCU_I2C0 and
  WKUP_I2C0), an external pullup is recommended irrespective of peripheral
  usage and IO configuration.
  Refer Pin Connectivity Requirements section of SoC data sheet
sheet 9
- GPIO MAPPING TABLE
sheet 10
- USB TYPE-C PD CONTROLLER AND POWER SUPPLY
- Silk: TYPE-C PWR
- TYPE-C DUAL PD CONTROLLER
- POWER INDICATION LED: VBUS_TYPEC1
- D-Note:-
  Ok to use a 1K
  standard 5%
  tolerance resistor
- BP_NoWait
  Safe Configuration
- R-Note
  This is a supply
  negotiation
  indicator.
  On indicates
  success.
- EXTERNAL POWER PATH FOR SOURCING, 5V/0.5A
- I2C Slave
   Address
- Port1
- Port2
- I2C2(Default)
- 0x38
- 0x3F
- I2C1
- 0x20
- 0x24
- SPI EEPROM & PROGRAMMING HEADER
